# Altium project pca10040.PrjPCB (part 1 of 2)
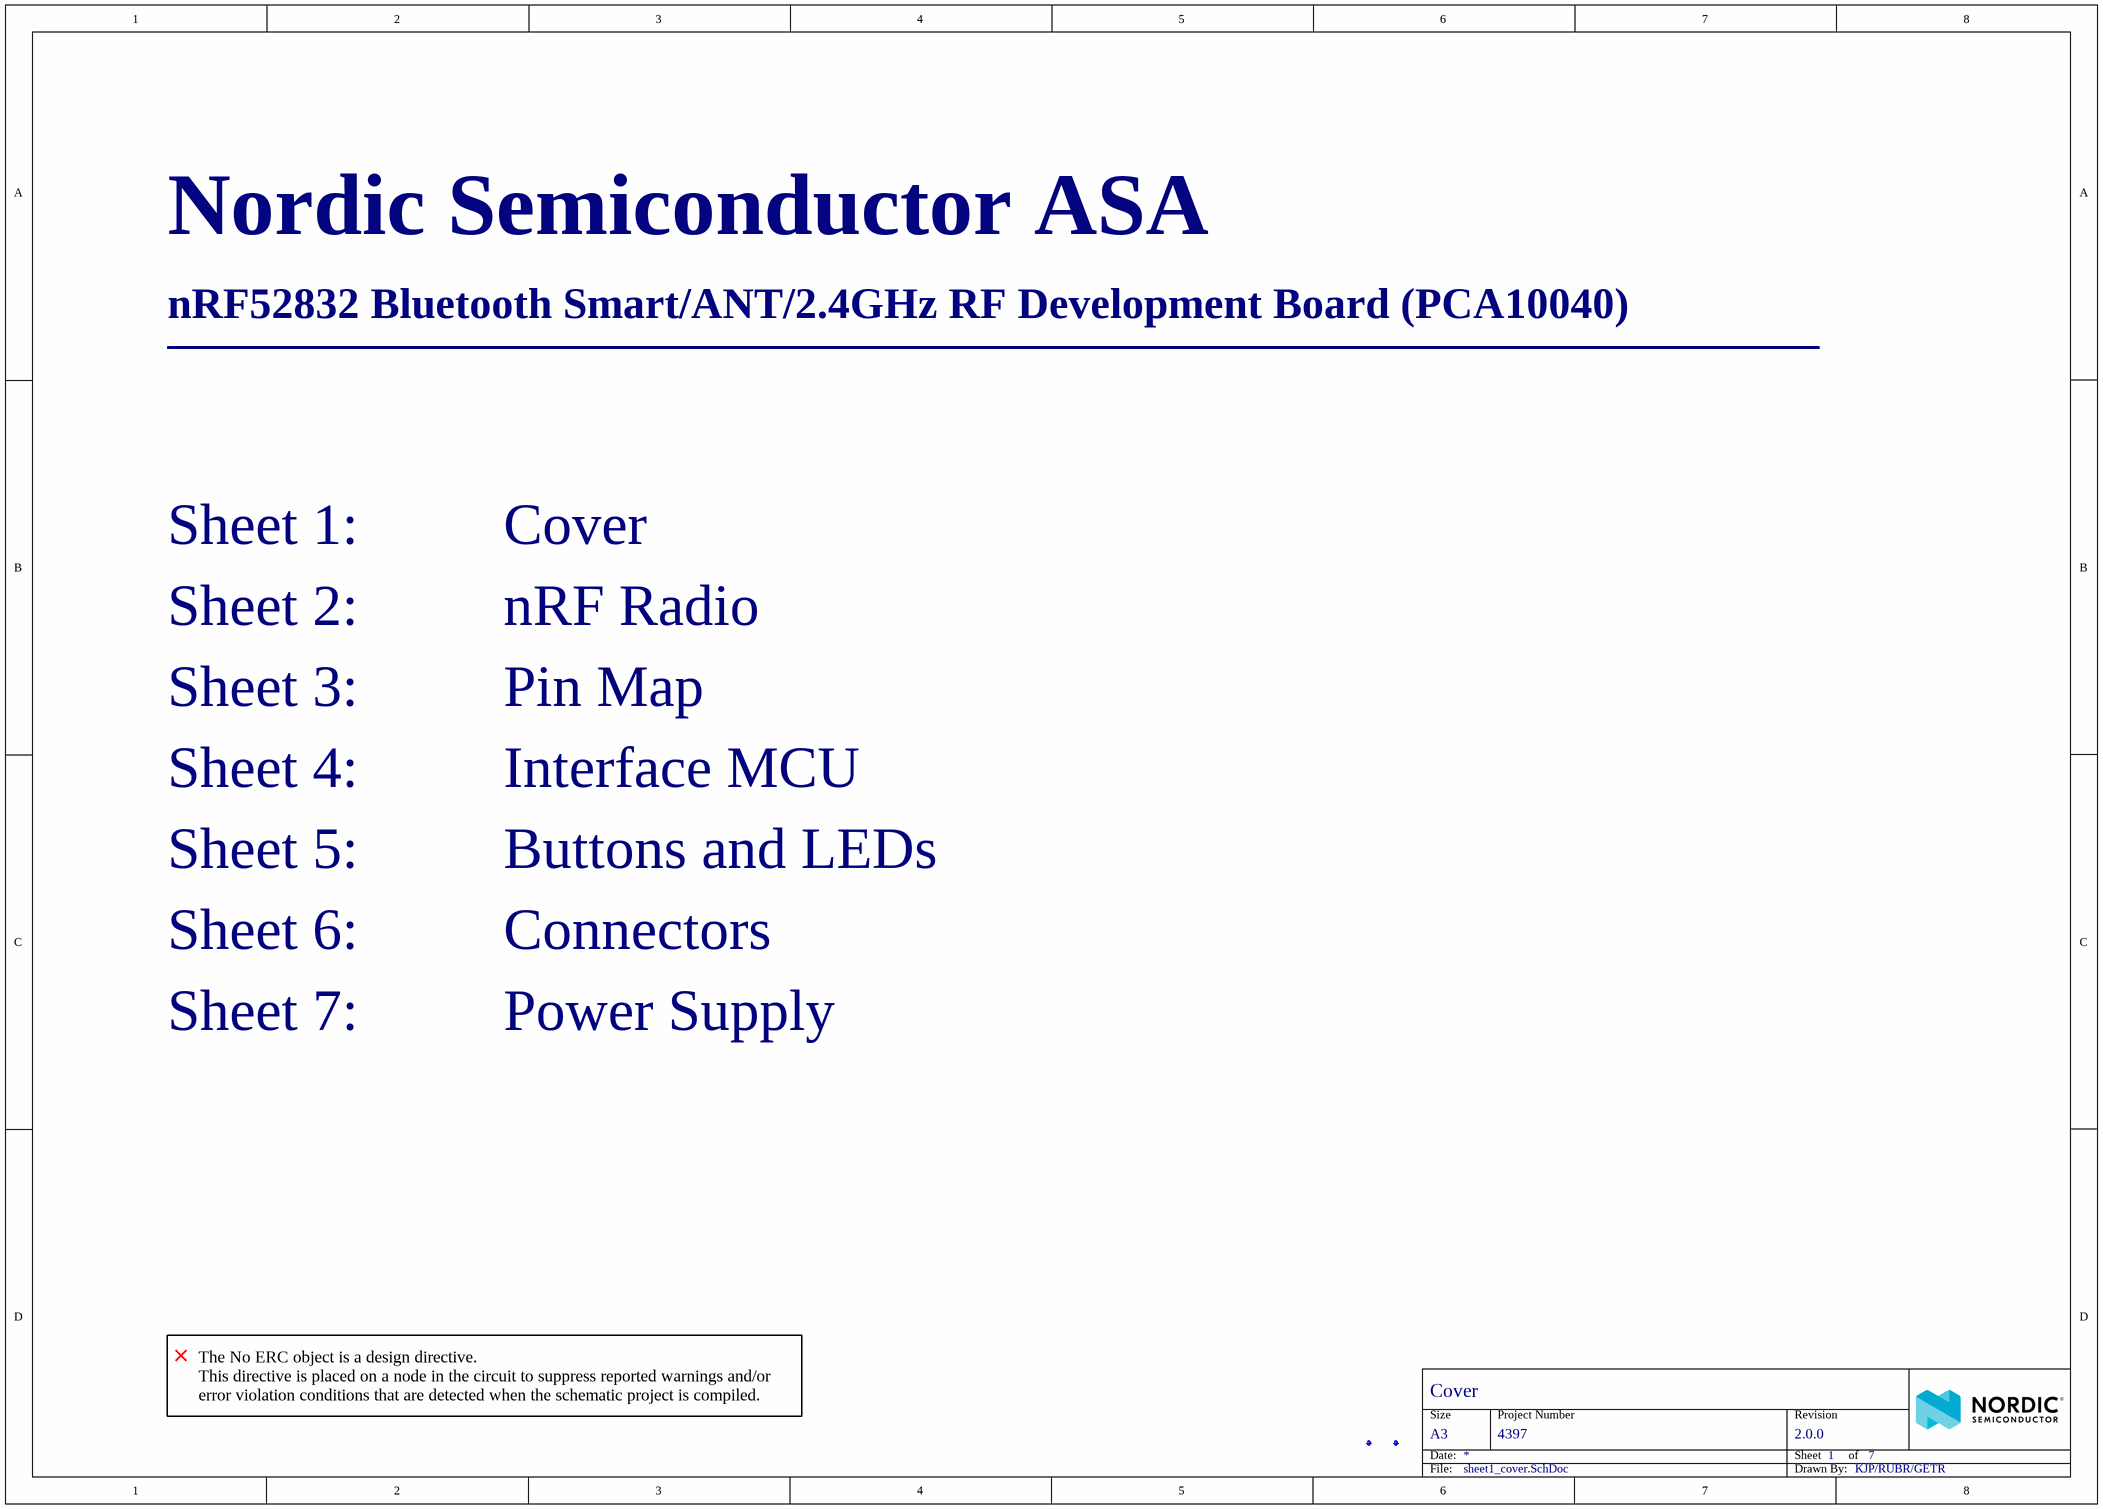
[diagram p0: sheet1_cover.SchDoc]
7 sheets, 248 parts. Net scope: global (net labels, ports and power ports of the same name join across sheets).
Board file: 400150.PcbDoc
Sheets:
  sheet1_cover.SchDoc
  sheet2_radio.SchDoc
  sheet3_pin_map.SchDoc
  sheet4_interface_mcu.SchDoc
  sheet5_buttons_and_leds.SchDoc
  sheet6_connectors.SchDoc
  sheet7_power_supply.SchDoc

## Sheet sheet1_cover.SchDoc: Cover
size A3; Organization: Nordic Semiconductor; DocumentNumber: 1; Revision: 2.0.0; SheetNumber: 1; SheetTotal: 7; CompanyName: Nordic Semiconductor; DrawnBy: KJP/RUBR/GETR; ProjectNumber: 4397; DocumentSize: A3; PCBRevision: 0111GETR; PCAName: PCA10040; PCBNumber: 400150

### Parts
Fid1  Fiducial mark  [Fiducial]  (value not drawn)
Fid2  Fiducial mark  [Fiducial]  (value not drawn)

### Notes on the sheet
- Nordic Semiconductor ASA
- nRF52832 Bluetooth Smart/ANT/2.4GHz RF Development Board (PCA10040)
- ________________________________________________________
- Sheet 1:          Cover
- Sheet 2:          nRF Radio
- Sheet 3:          Pin Map
- Sheet 4:          Interface MCU
- Sheet 5:          Buttons and LEDs
- Sheet 6:          Connectors
- Sheet 7:          Power Supply
- The No ERC object is a design directive.
  This directive is placed on a node in the circuit to suppress reported warnings and/or error violation conditions that are detected when the schematic project is compiled.

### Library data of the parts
Fid1 Fid2 = Fid-Mark: Artikkelnr Noca: N.A.

## Sheet sheet2_radio.SchDoc: nRF Radio
size A4; Organization: Nordic Semiconductor; DocumentNumber: 2; Revision: 2.0.0; SheetNumber: 2; SheetTotal: 7; CompanyName: Nordic Semiconductor; DrawnBy: KJP/RUBR/GETR; ProjectNumber: 4397; PCBRevision: 0111GETR; DocumentSize: A4; PCAName: PCA10040; PCBNumber: 400150
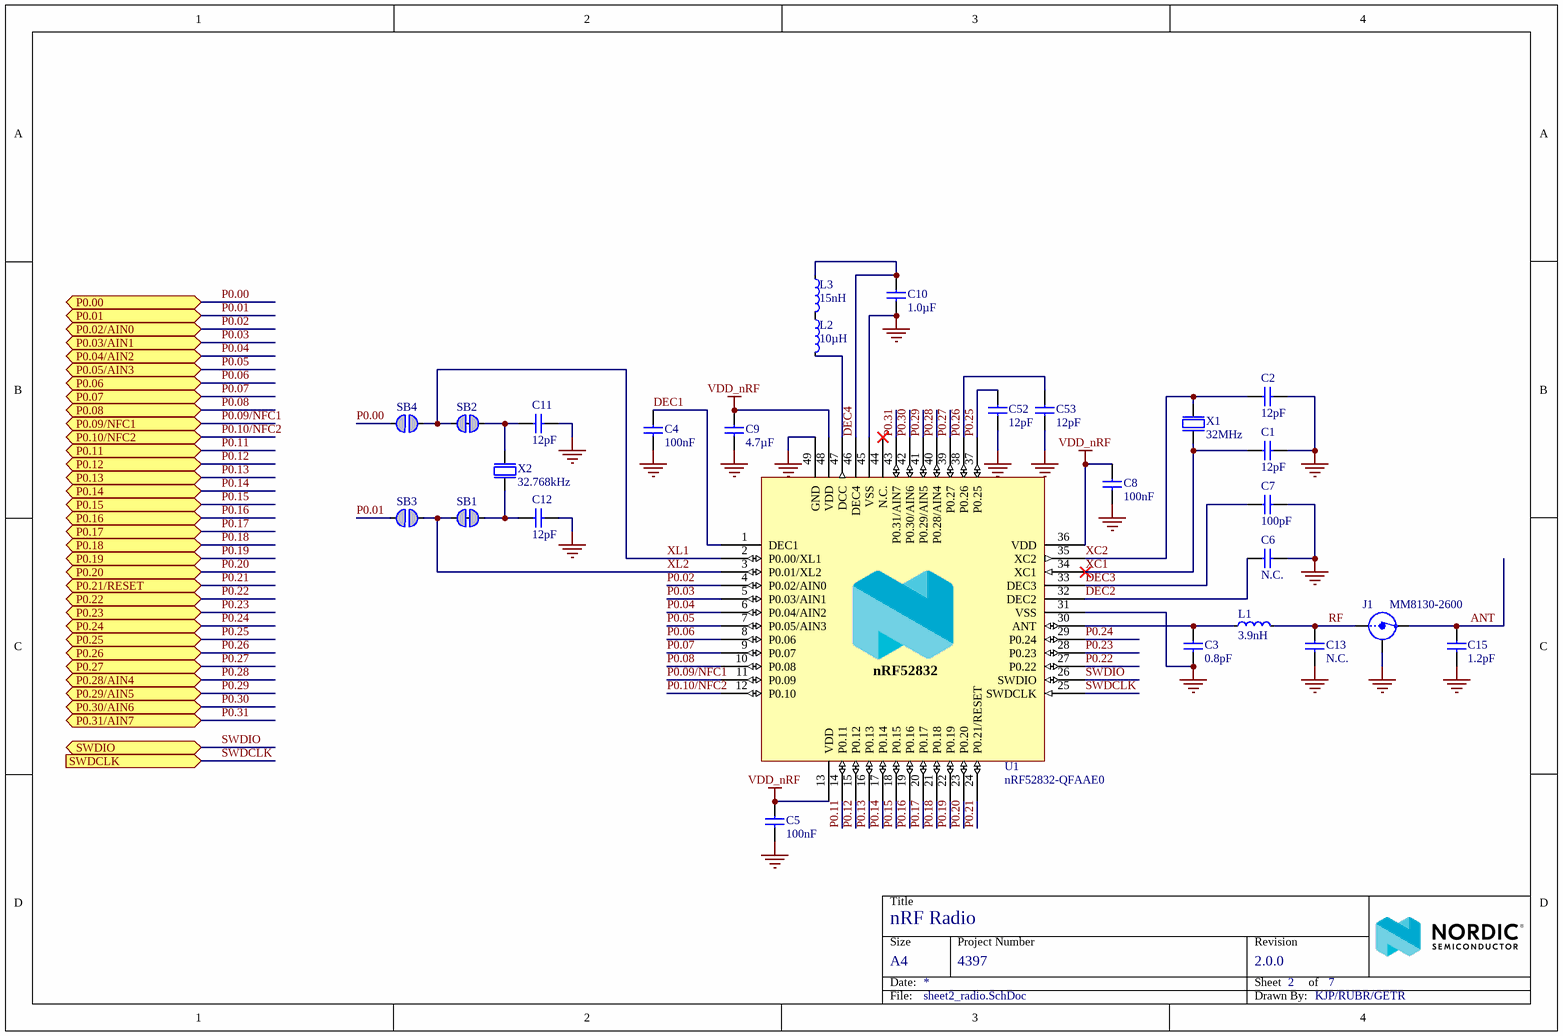
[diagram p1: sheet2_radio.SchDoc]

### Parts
C1  12pF  [CAPC1005X04L]
C2  12pF  [CAPC1005X04L]
C3  0.8pF  [CAPC1005X04L]
C4  100nF  [CAPC1005X04L]
C5  100nF  [CAPC1005X04L]
C6  N.C.  [CAPC1005X04L]
C7  100pF  [CAPC1005X04L]
C8  100nF  [CAPC1005X04L]
C9  4.7µF  [CAPC1608X06L]
C10  1.0µF  [CAPC1608X06L]
C11  12pF  [CAPC1005X04L]
C12  12pF  [CAPC1005X04L]
C13  N.C.  [CAPC1005X04L]
C15  1.2pF  [CAPC1005X04L]
C52  12pF  [CAPC1005X04L]
C53  12pF  [CAPC1005X04L]
J1  MM8130-2600  [COAXIAL-SWF]
L1  3.9nH  [INDC1005X04L]
L2  10µH  [INDC1608X06L]
L3  15nH  [INDC1005X04L]
SB1  Solderbridge  [Solderbridge_Shorted]  (value not drawn)  (net tie, no BOM)
SB2  Solderbridge  [Solderbridge_Shorted]  (value not drawn)  (net tie, no BOM)
SB3  Solderbridge  [Solderbridge]  (value not drawn)  (no BOM)
SB4  Solderbridge  [Solderbridge]  (value not drawn)  (no BOM)
U1  nRF52832-QFAAE0  [QFN40P600X600X90-48N]
X1  32MHz  [BT-XTAL_2016]
X2  32.768kHz  [XTAL_3215]

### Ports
P0.00 (bidir), P0.01 (bidir), P0.02/AIN0 (bidir), P0.03/AIN1 (bidir), P0.04/AIN2 (bidir), P0.05/AIN3 (bidir), P0.06 (bidir), P0.07 (bidir), P0.08 (bidir), P0.09/NFC1 (bidir), P0.10/NFC2 (bidir), P0.11 (bidir), P0.12 (bidir), P0.13 (bidir), P0.14 (bidir), P0.15 (bidir), P0.16 (bidir), P0.17 (bidir), P0.18 (bidir), P0.19 (bidir), P0.20 (bidir), P0.21/RESET (bidir), P0.22 (bidir), P0.23 (bidir), P0.24 (bidir), P0.25 (bidir), P0.26 (bidir), P0.27 (bidir), P0.28/AIN4 (bidir), P0.29/AIN5 (bidir), P0.30/AIN6 (bidir), P0.31/AIN7 (bidir), SWDCLK (in), SWDIO (bidir)

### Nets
GND: C1.2 C2.2 C3.1 C4.2 C5.2 C6.2 C7.2 C8.2 C9.2 C10.1 C11.1 C12.1 C13.2 C15.2 C52.2 C53.2 J1.2(Shield) U1.31(VSS) U1.45(VSS) U1.49(GND) X1.2(GND) X1.4(GND)
VDD_nRF: C5.1 C8.1 C9.1 U1.13(VDD) U1.36(VDD) U1.48(VDD)
ANT: C15.1 J1.3(OUT)
DEC1: C4.1 U1.1(DEC1)
DEC2: C6.1 U1.32(DEC2)
DEC3: C7.1 U1.33(DEC3)
DEC4: C10.2 L3.1 U1.46(DEC4)
P0.00: SB4.2 ; port P0.00
P0.01: SB3.2 ; port P0.01
P0.02: U1.4(P0.02/AIN0) ; port P0.02/AIN0
P0.03: U1.5(P0.03/AIN1) ; port P0.03/AIN1
P0.04: U1.6(P0.04/AIN2) ; port P0.04/AIN2
P0.05: U1.7(P0.05/AIN3) ; port P0.05/AIN3
P0.06: U1.8(P0.06) ; port P0.06
P0.07: U1.9(P0.07) ; port P0.07
P0.08: U1.10(P0.08) ; port P0.08
P0.09/NFC1: U1.11(P0.09) ; port P0.09/NFC1
P0.10/NFC2: U1.12(P0.10) ; port P0.10/NFC2
P0.11: U1.14(P0.11) ; port P0.11
P0.12: U1.15(P0.12) ; port P0.12
P0.13: U1.16(P0.13) ; port P0.13
P0.14: U1.17(P0.14) ; port P0.14
P0.15: U1.18(P0.15) ; port P0.15
P0.16: U1.19(P0.16) ; port P0.16
P0.17: U1.20(P0.17) ; port P0.17
P0.18: U1.21(P0.18) ; port P0.18
P0.19: U1.22(P0.19) ; port P0.19
P0.20: U1.23(P0.20) ; port P0.20
P0.21: U1.24(P0.21/RESET) ; port P0.21/RESET
P0.22: U1.27(P0.22) ; port P0.22
P0.23: U1.28(P0.23) ; port P0.23
P0.24: U1.29(P0.24) ; port P0.24
P0.25: C52.1 U1.37(P0.25) ; port P0.25
P0.26: C53.1 U1.38(P0.26) ; port P0.26
P0.27: U1.39(P0.27) ; port P0.27
P0.28: U1.40(P0.28/AIN4) ; port P0.28/AIN4
P0.29: U1.41(P0.29/AIN5) ; port P0.29/AIN5
P0.30: U1.42(P0.30/AIN6) ; port P0.30/AIN6
P0.31: U1.43(P0.31/AIN7) ; port P0.31/AIN7
RF: C13.1 J1.1(IN) L1.2
SWDCLK: U1.25(SWDCLK) ; port SWDCLK
SWDIO: U1.26(SWDIO) ; port SWDIO
XC1: C1.1 U1.34(XC1) X1.1(inp)
XC2: C2.1 U1.35(XC2) X1.3(out)
XL1: SB2.2 SB4.1 U1.2(P0.00/XL1)
XL2: SB1.2 SB3.1 U1.3(P0.01/XL2)
NetC3_2: C3.2 L1.1 U1.30(ANT)
NetC11_2: C11.2 SB2.1 X2.1(inp)
NetC12_2: C12.2 SB1.1 X2.2(out)
NetL2_1: L2.1 L3.2
NetL2_2: L2.2 U1.47(DCC)

Not connected (* = marked no-connect by the designer): U1 44(N.C.)*

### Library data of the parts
C1 C2 C11 C12 C52 C53 = C0402-12p: Capacitor, NP0, ±2%; Part number IPS: 00000002398; Note: 50V; Artikkelnr Noca: 20029159; Artikkelnr Simpro: N.A.
C3 = C0402-0.8p: Capacitor, NP0, ±5%; Part number IPS: 00000007782; Note: 50V; Artikkelnr Noca: 20029147; Artikkelnr Simpro: N.A.
C4 C5 C8 = C0402-100n: Capacitor, X7R, ±10%; Part number IPS: 00000005296; Note: 16V; Artikkelnr Noca: 20039200; Artikkelnr Simpro: N.A.
C6 C13 = C0402-N.C.: Not mounted; Note: Chip Cap; Artikkelnr Noca: N.A.; Assembly: Not mounted
C7 = C0402-100p: Capacitor, NP0, ±5%; Part number IPS: 00000002361; Note: 50V; Artikkelnr Noca: 20029135; Artikkelnr Simpro: N.A.
C9 = C0603-4µ7: Capacitor, X5R, ±10%; Part number IPS: 00000007783; Note: 6.3V; Artikkelnr Noca: 20069060; Artikkelnr Simpro: N.A.
C10 = C0603-1µ0: Capacitor, X7R, ±10%; Part number IPS: 00000000616; Note: 16V; Artikkelnr Noca: 20039335; Artikkelnr Simpro: N.A.
C15 = C0402-1.2p: Capacitor, NP0, ±0.1pF; Part number IPS: 00000005410; Note: 50V; Artikkelnr Noca: 20029157; Artikkelnr Simpro: N.A.
J1 = MM8130-2600: Coaxial Connector with Switch; Manufacturer: Murata; 2nd source part number: 81-MM8130-2600RA2; Artikkelnr Noca: 55029011; Artikkelnr Simpro: N.A.
L1 = L0402-3n9: Inductor, 170mA, ±0.1nH; Manufacturer: Murata; Manufacturer Part Number: LQP15MN3N9B02D; Part number IPS: 00000007793; Note: High frequency chip inductor ±5%; Artikkelnr Noca: 33029151; Artikkelnr Simpro: N.A.
L2 = L0603-10µ: Inductor, 80mA, ±10%; Manufacturer: Taiyo Yuden; Manufacturer Part Number: LBMF1608T100K; 2nd source part number: 178-6105; Part number IPS: 00000007794; Note: LBMF1608T100K 10µH 80mA 0603; Artikkelnr Noca: 33029314; Artikkelnr Simpro: N.A.
L3 = L0402-15n: Inductor, 320mA, ±5%; Manufacturer: Taiyo Yuden; Manufacturer Part Number: HK100515NJ-T; 2nd source part number: 658-1328; Part number IPS: 00000003215; Note: High frequency chip inductor ±10%; Artikkelnr Noca: 33029323; Artikkelnr Simpro: N.A.
SB1 SB2 = Solderbridge Shorted: Shorted Solderbridge; Artikkelnr Noca: N.A.
SB3 SB4 = Solderbridge: Artikkelnr Noca: N.A.
U1 = nRF52832-QFAAE0: Multi-protocol Bluetooth Low Energy, ANT and 2.4GHz proprietary system-on-chip; Manufacturer: Nordic Semiconductor; Artikkelnr Noca: N.A.
X1 = XTAL_SMD2016_32MHz_8pF_Epson: XTAL SMD 2016, 32MHz, Cl=8pF, Tol: ±10ppm, Stab: ±10ppm; Manufacturer: Epson Toyocom; Manufacturer Part Number: Q22FA12800025; Note: XTAL SMD 32.000MHz; Artikkelnr Noca: 22019238; Artikkelnr Simpro: N.A.
X2 = XTAL_FC-135 32.768k: XTAL SMD 3215, 32.768kHz, 9pF, ±20ppm; Manufacturer: Epson Toyocom; Manufacturer Part Number: FC-135 32.768KHZ ±20PPM,9.0PF; 2nd source part number: 127-8037; Note: XTAL SMD 32.768kHz, 3215; Artikkelnr Noca: 22019091; Artikkelnr Simpro: N.A.

## Sheet sheet3_pin_map.SchDoc: Pin Map
size A4; Organization: Nordic Semiconductor; DocumentNumber: 3; Revision: 2.0.0; SheetNumber: 3; SheetTotal: 7; CompanyName: Nordic Semiconductor; DrawnBy: RUBR/GETR; ProjectNumber: 4397; PCBRevision: 0111GETR; DocumentSize: A4; PCAName: PCA10040; PCBNumber: 400150
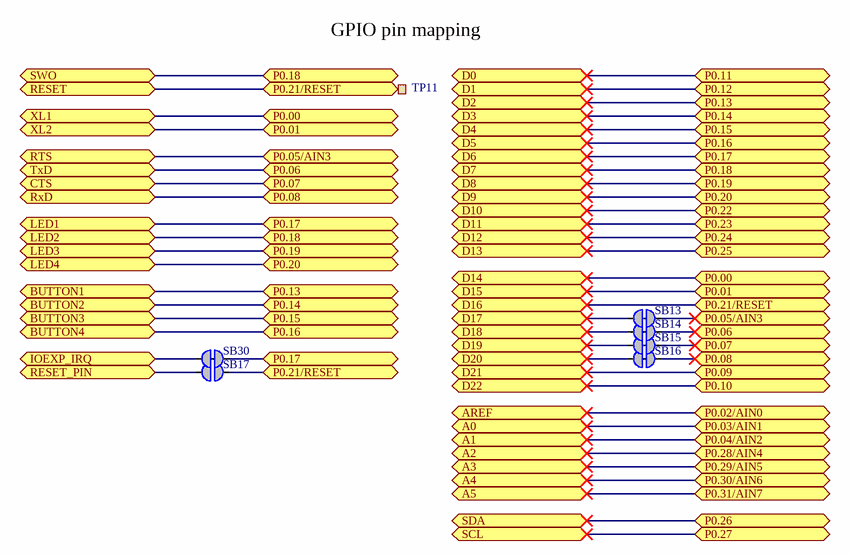
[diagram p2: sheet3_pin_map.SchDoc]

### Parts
SB13  Solderbridge  [Solderbridge_Shorted]  (value not drawn)  (net tie, no BOM)
SB14  Solderbridge  [Solderbridge_Shorted]  (value not drawn)  (net tie, no BOM)
SB15  Solderbridge  [Solderbridge_Shorted]  (value not drawn)  (net tie, no BOM)
SB16  Solderbridge  [Solderbridge_Shorted]  (value not drawn)  (net tie, no BOM)
SB17  Solderbridge  [Solderbridge]  (value not drawn)  (no BOM)
SB30  Solderbridge  [Solderbridge_Shorted]  (value not drawn)  (net tie, no BOM)
TP11  Ø1.0mm,SMD  [TP_SMD_Ø1.0mm]  (value not drawn)  (no BOM)

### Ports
A0 (bidir), A1 (bidir), A2 (bidir), A3 (bidir), A4 (bidir), A5 (bidir), AREF (bidir), BUTTON1 (bidir), BUTTON2 (bidir), BUTTON3 (bidir), BUTTON4 (bidir), CTS (bidir), D0 (bidir), D1 (bidir), D2 (bidir), D3 (bidir), D4 (bidir), D5 (bidir), D6 (bidir), D7 (bidir), D8 (bidir), D9 (bidir), D10 (bidir), D11 (bidir), D12 (bidir), D13 (bidir), D14 (bidir), D15 (bidir), D16 (bidir), D17 (bidir), D18 (bidir), D19 (bidir), D20 (bidir), D21 (bidir), D22 (bidir), IOEXP_IRQ (bidir), LED1 (bidir), LED2 (bidir), LED3 (bidir), LED4 (bidir), P0.00 (bidir), P0.01 (bidir), P0.02/AIN0 (bidir), P0.03/AIN1 (bidir), P0.04/AIN2 (bidir), P0.05/AIN3 (bidir), P0.06 (bidir), P0.07 (bidir), P0.08 (bidir), P0.09 (bidir), P0.10 (bidir), P0.11 (bidir), P0.12 (bidir), P0.13 (bidir), P0.14 (bidir), P0.15 (bidir), P0.16 (bidir), P0.17 (bidir), P0.18 (bidir), P0.19 (bidir), P0.20 (bidir), P0.21/RESET (bidir), P0.22 (bidir), P0.23 (bidir), P0.24 (bidir), P0.25 (bidir), P0.26 (bidir), P0.27 (bidir), P0.28/AIN4 (bidir), P0.29/AIN5 (bidir), P0.30/AIN6 (bidir), P0.31/AIN7 (bidir), RESET (bidir), RESET_PIN (bidir), RTS (bidir), RxD (bidir), SCL (bidir), SDA (bidir), SWO (bidir), TxD (bidir), XL1 (bidir), XL2 (bidir)

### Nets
D17: SB13.1 ; port D17
D18: SB14.1 ; port D18
D19: SB15.1 ; port D19
D20: SB16.1 ; port D20
D21: port D21, port P0.09
D22: port D22, port P0.10
IOEXP_IRQ: SB30.2 ; port IOEXP_IRQ
P0.00: port P0.00, port XL1, port D14
P0.01: port P0.01, port XL2, port D15
P0.02: port AREF, port P0.02/AIN0
P0.03: port A0, port P0.03/AIN1
P0.04: port A1, port P0.04/AIN2
P0.05: SB13.2 ; port P0.05/AIN3, port RTS
P0.06: SB14.2 ; port P0.06, port TxD
P0.07: SB15.2 ; port P0.07, port CTS
P0.08: SB16.2 ; port P0.08, port RxD
P0.11: port D0, port P0.11
P0.12: port D1, port P0.12
P0.13: port P0.13, port BUTTON1, port D2
P0.14: port P0.14, port BUTTON2, port D3
P0.15: port P0.15, port BUTTON3, port D4
P0.16: port P0.16, port BUTTON4, port D5
P0.17: SB30.1 ; port LED1, port D6, port P0.17
P0.18: port SWO, port P0.18, port LED2, port D7
P0.19: port LED3, port D8, port P0.19
P0.20: port LED4, port D9, port P0.20
P0.21: SB17.2 TP11.1 ; port RESET, port P0.21/RESET, port D16
P0.22: port D10, port P0.22
P0.23: port D11, port P0.23
P0.24: port D12, port P0.24
P0.25: port D13, port P0.25
P0.26: port P0.26, port SDA
P0.27: port P0.27, port SCL
P0.28: port A2, port P0.28/AIN4
P0.29: port A3, port P0.29/AIN5
P0.30: port A4, port P0.30/AIN6
P0.31: port A5, port P0.31/AIN7
RESET_PIN: SB17.1 ; port RESET_PIN

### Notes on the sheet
- (near TP11) GPIO pin mapping

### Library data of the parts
SB13-SB16 SB30 = Solderbridge Shorted: as SB1 on sheet sheet2_radio
SB17 = Solderbridge: Artikkelnr Noca: N.A.
TP11 = TP_SMD_Ø1.0MM: 1.0mm circular SMD testpad; Manufacturer: Nordic Semiconductor; Artikkelnr Noca: N.A.

## Sheet sheet4_interface_mcu.SchDoc: Interface MCU
size A3; Organization: Nordic Semiconductor; DocumentNumber: 4; Revision: 2.0.0; SheetNumber: 4; SheetTotal: 7; CompanyName: Nordic Semiconductor; DrawnBy: KJP/RUBR/GETR; ProjectNumber: 4397; PCAName: PCA10040; PCBRevision: 0111GETR; DocumentSize: A3; PCBNumber: 400150
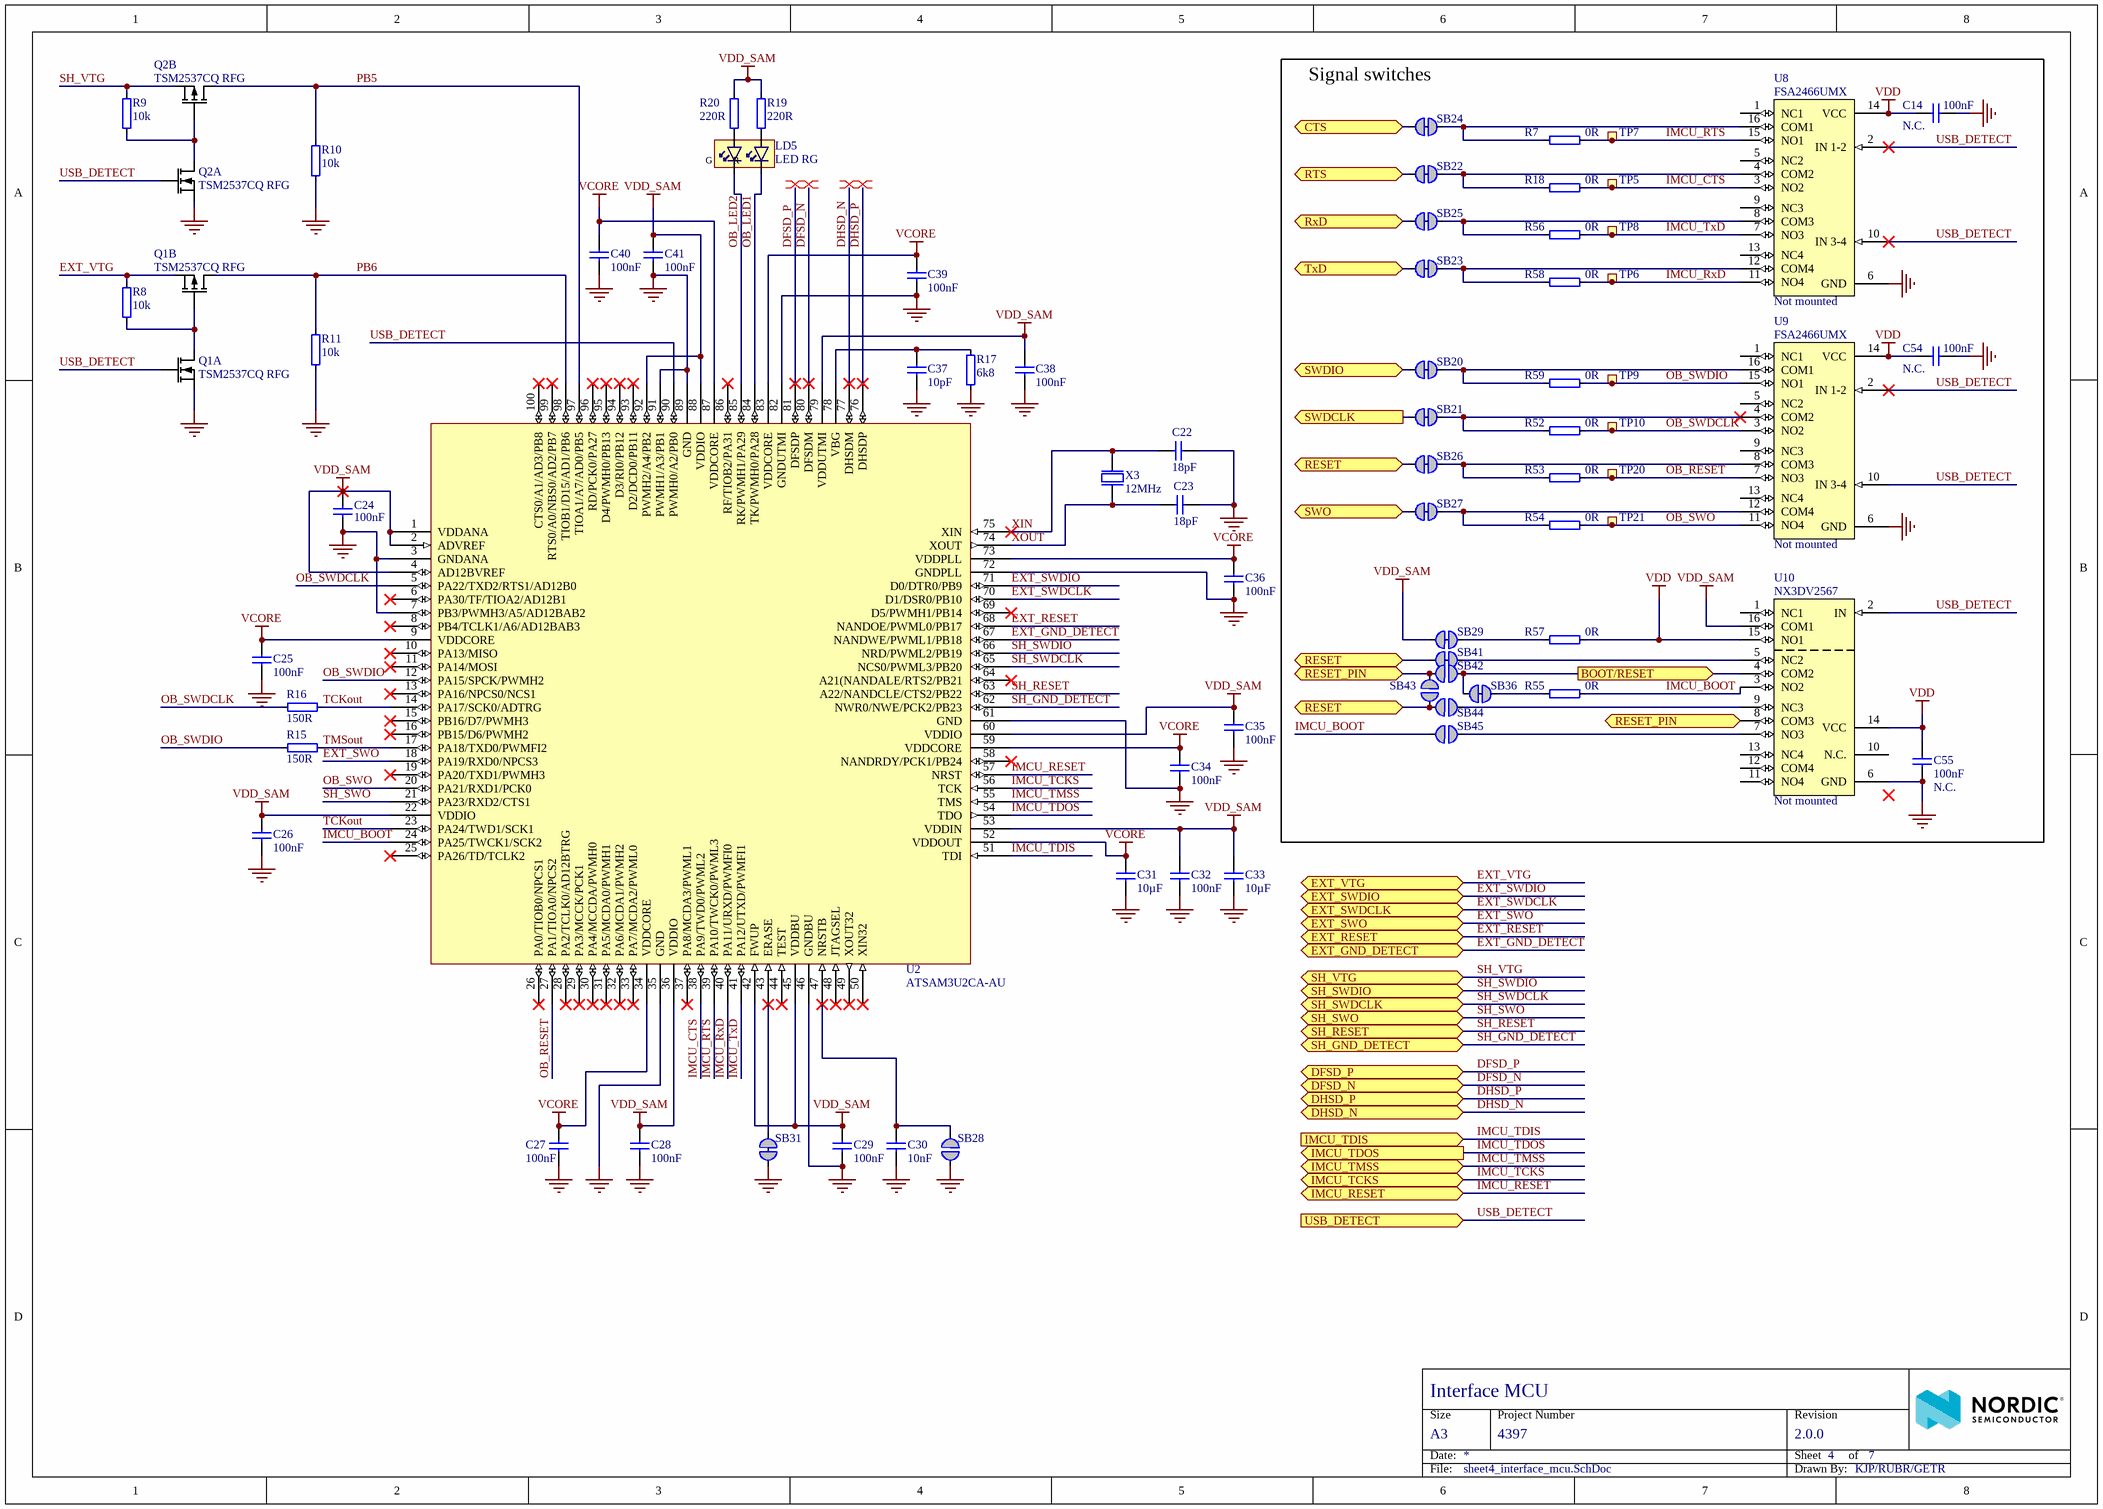
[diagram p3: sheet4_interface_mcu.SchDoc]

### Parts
C14  100nF  Assembly: N.C.  [CAPC1005X04L]
C22  18pF  [CAPC1005X04L]
C23  18pF  [CAPC1005X04L]
C24  100nF  [CAPC1005X04L]
C25  100nF  [CAPC1005X04L]
C26  100nF  [CAPC1005X04L]
C27  100nF  [CAPC1005X04L]
C28  100nF  [CAPC1005X04L]
C29  100nF  [CAPC1005X04L]
C30  10nF  [CAPC1005X04L]
C31  10µF  [CAPC1608X06L]
C32  100nF  [CAPC1005X04L]
C33  10µF  [CAPC1608X06L]
C34  100nF  [CAPC1005X04L]
C35  100nF  [CAPC1005X04L]
C36  100nF  [CAPC1005X04L]
C37  10pF  [CAPC1005X04L]
C38  100nF  [CAPC1005X04L]
C39  100nF  [CAPC1005X04L]
C40  100nF  [CAPC1005X04L]
C41  100nF  [CAPC1005X04L]
C54  100nF  Assembly: N.C.  [CAPC1005X04L]
C55  100nF  Assembly: N.C.  [CAPC1005X04L]
LD5  LED RG  [LED_DUAL_0606]
Q1  TSM2537CQ RFG  [DFN65P200X200X80_HS-6N]  (parts A,B of 2)
Q2  TSM2537CQ RFG  [DFN65P200X200X80_HS-6N]  (parts A,B of 2)
R7  0R  [RESC1005X04L]
R8  10k  [RESC1005X04L]
R9  10k  [RESC1005X04L]
R10  10k  [RESC1005X04L]
R11  10k  [RESC1005X04L]
R15  150R  [RESC1005X04L]
R16  150R  [RESC1005X04L]
R17  6k8  [RESC1005X04L]
R18  0R  [RESC1005X04L]
R19  220R  [RESC0603X03L_C]
R20  220R  [RESC0603X03L_C]
R52  0R  [RESC1005X04L]
R53  0R  [RESC1005X04L]
R54  0R  [RESC1005X04L]
R55  0R  [RESC1005X04L]
R56  0R  [RESC1005X04L]
R57  0R  [RESC1005X04L]
R58  0R  [RESC1005X04L]
R59  0R  [RESC1005X04L]
SB20  Solderbridge  [Solderbridge_Shorted]  (value not drawn)  (net tie, no BOM)
SB21  Solderbridge  [Solderbridge_Shorted]  (value not drawn)  (net tie, no BOM)
SB22  Solderbridge  [Solderbridge_Shorted]  (value not drawn)  (net tie, no BOM)
SB23  Solderbridge  [Solderbridge_Shorted]  (value not drawn)  (net tie, no BOM)
SB24  Solderbridge  [Solderbridge_Shorted]  (value not drawn)  (net tie, no BOM)
SB25  Solderbridge  [Solderbridge_Shorted]  (value not drawn)  (net tie, no BOM)
SB26  Solderbridge  [Solderbridge_Shorted]  (value not drawn)  (net tie, no BOM)
SB27  Solderbridge  [Solderbridge_Shorted]  (value not drawn)  (net tie, no BOM)
SB28  Solderbridge  [Solderbridge]  (value not drawn)  (no BOM)
SB29  Solderbridge  [Solderbridge_Shorted]  (value not drawn)  (net tie, no BOM)
SB31  Solderbridge  [Solderbridge_Shorted]  (value not drawn)  (net tie, no BOM)
SB36  Solderbridge  [Solderbridge_Shorted]  (value not drawn)  (net tie, no BOM)
SB41  Solderbridge  [Solderbridge_Shorted]  (value not drawn)  (net tie, no BOM)
SB42  Solderbridge  [Solderbridge]  (value not drawn)  (no BOM)
SB43  Solderbridge  [Solderbridge]  (value not drawn)  (no BOM)
SB44  Solderbridge  [Solderbridge]  (value not drawn)  (no BOM)
SB45  Solderbridge  [Solderbridge]  (value not drawn)  (no BOM)
TP5  Ø1.0mm,SMD  [TP_SMD_Ø1.0mm]  (value not drawn)  (no BOM)
TP6  Ø1.0mm,SMD  [TP_SMD_Ø1.0mm]  (value not drawn)  (no BOM)
TP7  Ø1.0mm,SMD  [TP_SMD_Ø1.0mm]  (value not drawn)  (no BOM)
TP8  Ø1.0mm,SMD  [TP_SMD_Ø1.0mm]  (value not drawn)  (no BOM)
TP9  Ø1.0mm,SMD  [TP_SMD_Ø1.0mm]  (value not drawn)  (no BOM)
TP10  Ø1.0mm,SMD  [TP_SMD_Ø1.0mm]  (value not drawn)  (no BOM)
TP20  Ø1.0mm,SMD  [TP_SMD_Ø1.0mm]  (value not drawn)  (no BOM)
TP21  Ø1.0mm,SMD  [TP_SMD_Ø1.0mm]  (value not drawn)  (no BOM)
U2  ATSAM3U2CA-AU  [TSQFP50P1600X1600X160-100N]
U8  FSA2466UMX  Assembly: Not mounted  [XQFN40P180X260X50-16N]
U9  FSA2466UMX  Assembly: Not mounted  [XQFN40P180X260X50-16N]
U10  NX3DV2567  Assembly: Not mounted  [XQFN40P180X260X50-16N]
X3  12MHz  [BT-XTAL_3225]

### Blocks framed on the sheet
Signal switches: C14 C54 C55 R7 R18 R52-R59 SB20-SB27 SB29 SB36 SB41-SB45 TP5-TP10 TP20 TP21 U8-U10

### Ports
BOOT/RESET (out), CTS (bidir), DFSD_N (bidir), DFSD_P (bidir), DHSD_N (bidir), DHSD_P (bidir), EXT_GND_DETECT (bidir), EXT_RESET (bidir), EXT_SWDCLK (bidir), EXT_SWDIO (bidir), EXT_SWO (bidir), EXT_VTG (bidir), IMCU_RESET (bidir), IMCU_TCKS (bidir), IMCU_TDIS (in), IMCU_TDOS (out), IMCU_TMSS (bidir), RESET (bidir), RESET_PIN (bidir), RTS (bidir), RxD (bidir), SH_GND_DETECT (bidir), SH_RESET (bidir), SH_SWDCLK (bidir), SH_SWDIO (bidir), SH_SWO (bidir), SH_VTG (bidir), SWDCLK (out), SWDIO (bidir), SWO (bidir), TxD (bidir), USB_DETECT (in)

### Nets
GND: C14.1 C22.2 C23.2 C24.1 C25.1 C26.1 C27.1 C28.1 C29.1 C30.1 C31.1 C32.1 C33.1 C34.1 C35.1 C36.2 C37.1 C38.1 C39.1 C40.1 C41.1 C54.1 C55.1 Q1.1(S1) Q2.1(S1) R10.1 R11.1 R17.1 SB28.2 SB31.2 U2.3(GNDANA) U2.7(PB3/PWMH3/A5/AD12BAB2) U2.35(GND) U2.46(GNDBU) U2.61(GND) U2.72(GNDPLL) U2.82(GNDUTMI) U2.89(GND) U2.91(PWMH1/A3/PB1) U8.6(GND) U9.6(GND) U10.6(GND) X3.2(GND) X3.4(GND)
VCORE: C25.2 C27.2 C31.2 C34.2 C36.1 C39.2 C40.2 U2.9(VDDCORE) U2.34(VDDCORE) U2.52(VDDOUT) U2.59(VDDCORE) U2.73(VDDPLL) U2.83(VDDCORE) U2.87(VDDCORE)
VDD: C14.2 C54.2 C55.2 R57.2 U8.14(VCC) U9.14(VCC) U10.14(VCC) U10.15(NO1)
VDD_SAM: C24.2 C26.2 C28.2 C29.2 C32.2 C33.2 C35.2 C38.2 C41.2 R19.2 R20.2 SB29.2 U2.1(VDDANA) U2.2(ADVREF) U2.4(AD12BVREF) U2.22(VDDIO) U2.36(VDDIO) U2.42(FWUP) U2.45(VDDBU) U2.53(VDDIN) U2.60(VDDIO) U2.79(VDDUTMI) U2.88(VDDIO) U2.92(PWMH2/A4/PB2) U10.16(COM1)
BOOT/RESET: SB36.2 SB42.1 U10.4(COM2) ; port BOOT/RESET
DFSD_N: U2.80(DFSDM) ; port DFSD_N
DFSD_P: U2.81(DFSDP) ; port DFSD_P
DHSD_N: U2.77(DHSDM) ; port DHSD_N
DHSD_P: U2.76(DHSDP) ; port DHSD_P
EXT_GND_DETECT: U2.67(NANDWE/PWML1/PB18) ; port EXT_GND_DETECT
EXT_RESET: U2.68(NANDOE/PWML0/PB17) ; port EXT_RESET
EXT_SWDCLK: U2.70(D1/DSR0/PB10) ; port EXT_SWDCLK
EXT_SWDIO: U2.71(D0/DTR0/PB9) ; port EXT_SWDIO
EXT_SWO: U2.18(PA19/RXD0/NPCS3) ; port EXT_SWO
EXT_VTG: Q1.4(S2) R8.1 ; port EXT_VTG
IMCU_BOOT: R55.2 SB45.2 U2.24(PA25/TWCK1/SCK2) U10.3(NO2)
IMCU_CTS: R18.2 TP5.1 U2.38(PA9/TWD0/PWML2) U8.3(NO2)
IMCU_RESET: U2.57(NRST) ; port IMCU_RESET
IMCU_RTS: R7.2 TP7.1 U2.39(PA10/TWCK0/PWML3) U8.15(NO1)
IMCU_RxD: R58.2 TP6.1 U2.40(PA11/URXD/PWMFI0) U8.11(NO4)
IMCU_TCKS: U2.56(TCK) ; port IMCU_TCKS
IMCU_TDIS: U2.51(TDI) ; port IMCU_TDIS
IMCU_TDOS: U2.54(TDO) ; port IMCU_TDOS
IMCU_TMSS: U2.55(TMS) ; port IMCU_TMSS
IMCU_TxD: R56.2 TP8.1 U2.41(PA12/UTXD/PWMFI1) U8.7(NO3)
OB_LED1: LD5.4(C1) U2.84(TK/PWMH0/PA28)
OB_LED2: LD5.3(C2) U2.85(RK/PWMH1/PA29)
OB_RESET: R53.2 TP20.1 U2.27(PA1/TIOA0/NPCS2) U9.7(NO3)
OB_SWDCLK: R16.2 R52.2 TP10.1 U2.5(PA22/TXD2/RTS1/AD12B0) U9.3(NO2)
OB_SWDIO: R15.2 R59.2 TP9.1 U2.12(PA15/SPCK/PWMH2) U9.15(NO1)
OB_SWO: R54.2 TP21.1 U2.20(PA21/RXD1/PCK0) U9.11(NO4)
P0.05: SB22.2 ; port RTS
P0.06: SB23.2 ; port TxD
P0.07: SB24.2 ; port CTS
P0.08: SB25.2 ; port RxD
P0.18: SB27.2 ; port SWO
P0.21: SB26.2 SB41.2 SB43.2 SB44.2 ; port RESET
PB5: Q2.3(D2) R10.2 U2.97(TIOA1/A7/AD0/PB5)
PB6: Q1.3(D2) R11.2 U2.98(TIOB1/D15/AD1/PB6)
RESET_PIN: SB42.2 SB43.1 U10.8(COM3) ; port RESET_PIN
SH_GND_DETECT: U2.62(NWR0/NWE/PCK2/PB23) ; port SH_GND_DETECT
SH_RESET: U2.63(A22/NANDCLE/CTS2/PB22) ; port SH_RESET
SH_SWDCLK: U2.65(NCS0/PWML3/PB20) ; port SH_SWDCLK
SH_SWDIO: U2.66(NRD/PWML2/PB19) ; port SH_SWDIO
SH_SWO: U2.21(PA23/RXD2/CTS1) ; port SH_SWO
SH_VTG: Q2.4(S2) R9.1 ; port SH_VTG
SWDCLK: SB21.2 ; port SWDCLK
SWDIO: SB20.2 ; port SWDIO
TCKout: R16.1 U2.14(PA17/SCK0/ADTRG) U2.23(PA24/TWD1/SCK1)
TMSout: R15.1 U2.17(PA18/TXD0/PWMFI2)
USB_DETECT: Q1.2(G1) Q2.2(G1) U2.90(PWMH0/A2/PB0) U8.2(IN_1-2) U8.10(IN_3-4) U9.2(IN_1-2) U9.10(IN_3-4) U10.2(IN) ; port USB_DETECT
XIN: C22.1 U2.75(XIN) X3.3(out)
XOUT: C23.1 U2.74(XOUT) X3.1(inp)
NetC30_2: C30.2 SB28.1 U2.47(NRSTB)
NetC37_2: C37.2 R17.2 U2.78(VBG)
NetLD5_1: LD5.1(A2) R20.1
NetLD5_2: LD5.2(A1) R19.1
NetQ1_5: Q1.5(G2) Q1.6(D1) R8.2
NetQ2_5: Q2.5(G2) Q2.6(D1) R9.2
NetR7_1: R7.1 SB24.1 U8.16(COM1)
NetR18_1: R18.1 SB22.1 U8.4(COM2)
NetR52_1: R52.1 SB21.1 U9.4(COM2)
NetR53_1: R53.1 SB26.1 U9.8(COM3)
NetR54_1: R54.1 SB27.1 U9.12(COM4)
NetR55_1: R55.1 SB36.1
NetR56_1: R56.1 SB25.1 U8.8(COM3)
NetR57_1: R57.1 SB29.1
NetR58_1: R58.1 SB23.1 U8.12(COM4)
NetR59_1: R59.1 SB20.1 U9.16(COM1)
NetSB31_1: SB31.1 U2.43(ERASE)
NetSB41_1: SB41.1 U10.5(NC2)
NetSB44_1: SB44.1 U10.9(NC3)
NetSB45_1: SB45.1 U10.7(NO3)

Not connected (* = marked no-connect by the designer): U2 6(PA30/TF/TIOA2/AD12B1)* 8(PB4/TCLK1/A6/AD12BAB3)* 10(PA13/MISO)* 11(PA14/MOSI)* 13(PA16/NPCS0/NCS1)* 15(PB16/D7/PWMH3)* 16(PB15/D6/PWMH2)* 19(PA20/TXD1/PWMH3)* 25(PA26/TD/TCLK2)* 26(PA0/TIOB0/NPCS1)* 28(PA2/TCLK0/AD12BTRG)* 29(PA3/MCCK/PCK1)* 30(PA4/MCCDA/PWMH0)* 31(PA5/MCDA0/PWMH1)* 32(PA6/MCDA1/PWMH2)* 33(PA7/MCDA2/PWML0)* 37(PA8/MCDA3/PWML1)* 44(TEST)* 48(JTAGSEL)* 49(XOUT32)* 50(XIN32)* 58(NANDRDY/PCK1/PB24)* 64(A21(NANDALE/RTS2/PB21)* 69(D5/PWMH1/PB14)* 86(RF/TIOB2/PA31)* 93(D2/DCD0/PB11)* 94(D3/RI0/PB12)* 95(D4/PWMH0/PB13)* 96(RD/PCK0/PA27)* 99(RTS0/A0/NBS0/AD2/PB7)* 100(CTS0/A1/AD3/PB8)*; U8 1(NC1) 5(NC2) 9(NC3) 13(NC4); U9 1(NC1) 5(NC2) 9(NC3) 13(NC4); U10 1(NC1) 10(N.C.) 11(NO4) 12(COM4) 13(NC4)

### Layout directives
differential pair: DFSD_N, DFSD_P, DHSD_N, DHSD_P

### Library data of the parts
C14 C24-C29 C32 C34-C36 C38-C41 C54 C55 = C0402-100n: as C4 on sheet sheet2_radio
C22 C23 = C0402-18p: Capacitor, NP0, ±5%; Note: 50V; Artikkelnr Noca: 20029209; Artikkelnr Simpro: N.A.
C30 = C0402-10n: Capacitor, X7R, ±10%; Part number IPS: 00000007784; Note: 16V; Artikkelnr Noca: 20039166; Artikkelnr Simpro: N.A.
C31 C33 = C0603-10µ: Capacitor, X5R, ±20%; Part number IPS: 00000007785; Note: 6.3V; Artikkelnr Noca: 20039234; Artikkelnr Simpro: N.A.
C37 = C0402-10p: Capacitor, NP0, ±2%; 2nd source part number: 185-6064; Note: 50V; Artikkelnr Noca: 20029260; Artikkelnr Simpro: N.A.
LD5 = LTST-C195KGJRKT: Ultra bright AlInGaP Bi-Color LED; Manufacturer: Lite-On Inc; 2nd source part number: 859-LTST-C195KGJRKT; Artikkelnr Noca: 13019145; Artikkelnr Simpro: N.A.
Q1 Q2 = TSM2537CQ RFG: Dual N & P Ch MOFET, 11.6A/9A, 90mOhm max, 6.25W; Manufacturer: Taiwan Semiconductor; Artikkelnr Noca: N.A.
R7 R18 R52-R59 = R0402-0R: Resistor, ±5%, 0.063W; Note: Chip Res 5%; Artikkelnr Noca: 27049000; Artikkelnr Simpro: N.A.; Value Ohm: 0
R8-R11 = R0402-10k: Resistor, ±1%, 0.063W; Part number IPS: 00000002093; Note: Chip Res 1%; Artikkelnr Noca: 27049097; Artikkelnr Simpro: N.A.; Value Ohm: 10000
R15 R16 = R0402-150: Resistor, ±1%, 0.063W; Note: Chip Res 1%; Artikkelnr Noca: 27049053; Artikkelnr Simpro: N.A.; Value Ohm: 150
R17 = R0402-6k8: Resistor, ±1%, 0.063W; Note: Chip Res 1%; Artikkelnr Noca: 27049093; Artikkelnr Simpro: N.A.; Value Ohm: 6800
R19 R20 = R0201-220: Resistor, ±1%, 0.05W; Part number IPS: 00000000863; Note: Chip Res 1%; Artikkelnr Noca: N.A.
SB20-SB27 SB29 SB31 SB36 SB41 = Solderbridge Shorted: as SB1 on sheet sheet2_radio
SB28 SB42-SB45 = Solderbridge: Artikkelnr Noca: N.A.
TP5-TP10 TP20 TP21 = TP_SMD_Ø1.0MM: as TP11 on sheet sheet3_pin_map
U2 = ATSAM3U2CA-AU: IC MCU 32bit 128kB flash 100LQFP; Manufacturer: Atmel; 2nd source part number: 184-1662; Artikkelnr Noca: 15019073; Artikkelnr Simpro: N.A.
U8 U9 = FSA2466UMX: Data / Audio Low-Voltage Dual DPDT Analog Switch; Manufacturer: Fairchild Semiconductor; 2nd source part number: 512-FSA2466UMX; Artikkelnr Noca: 15070069; Artikkelnr Simpro: N.A.
U10 = NX3DV2567GU: Low-ohmic four-pole double-throw analog switch; Manufacturer: NXP Semiconductors; 2nd source part number: 771-NX3DV2567GU115; Part number IPS: 00000007816; Artikkelnr Noca: 15079317; Artikkelnr Simpro: N.A.
X3 = XTAL_SMD3225_12MHz_18pF_TXC: XTAL SMD 3225, 12MHz, Cl=18pF, Tol: ±30ppm, Stab: ±30ppm; Manufacturer: TXC Corporation; Manufacturer Part Number: 7M-12.000MAAJ-T; 2nd source part number: 184-2056; Note: XTAL SMD 12.000MHz; Artikkelnr Noca: 22019166; Artikkelnr Simpro: N.A.

## Sheet sheet5_buttons_and_leds.SchDoc: Buttons and LEDs
size A4; Organization: Nordic Semiconductor; DocumentNumber: 5; Revision: 2.0.0; SheetNumber: 5; SheetTotal: 7; CompanyName: Nordic Semiconductor; DrawnBy: KJP/RUBR/GETR; ProjectNumber: 4397; PCBRevision: 0111GETR; DocumentSize: A4; PCAName: PCA10040; PCBNumber: 400150
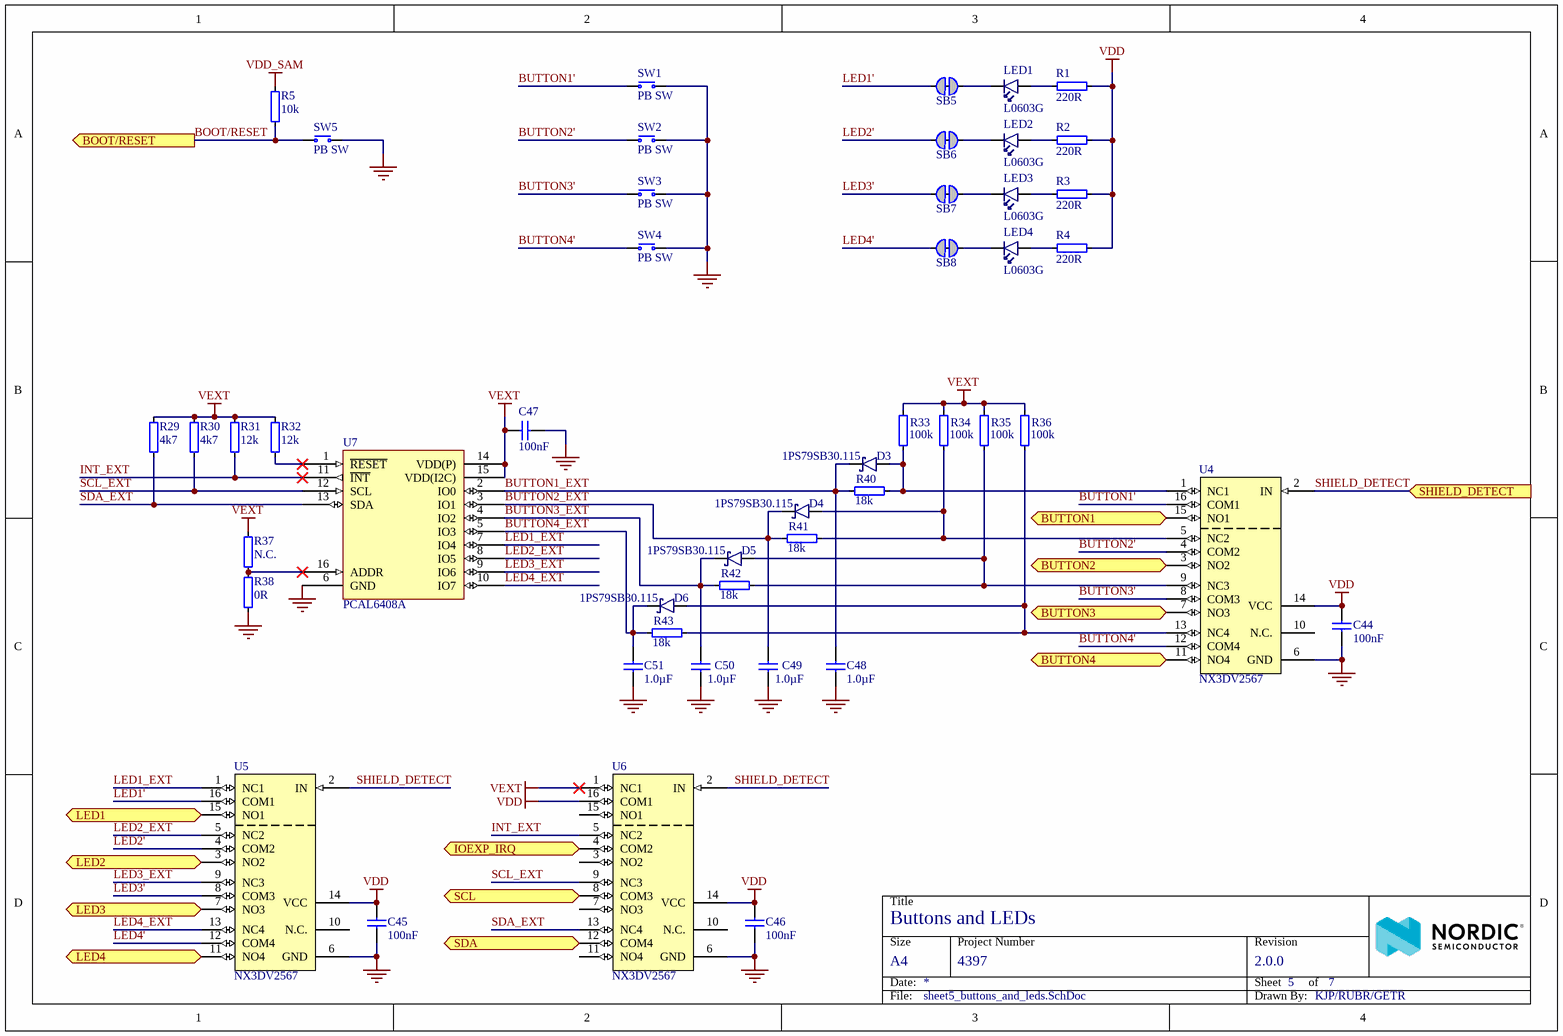
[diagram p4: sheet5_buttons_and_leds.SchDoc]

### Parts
C44  100nF  [CAPC1005X04L]
C45  100nF  [CAPC1005X04L]
C46  100nF  [CAPC1005X04L]
C47  100nF  [CAPC1005X04L]
C48  1.0µF  [CAPC1005X04L]
C49  1.0µF  [CAPC1005X04L]
C50  1.0µF  [CAPC1005X04L]
C51  1.0µF  [CAPC1005X04L]
D3  1PS79SB30.115  [SOD-523]
D4  1PS79SB30.115  [SOD-523]
D5  1PS79SB30.115  [SOD-523]
D6  1PS79SB30.115  [SOD-523]
LED1  L0603G  [LED_0603_G]
LED2  L0603G  [LED_0603_G]
LED3  L0603G  [LED_0603_G]
LED4  L0603G  [LED_0603_G]
R1  220R  [RESC1005X04L]
R2  220R  [RESC1005X04L]
R3  220R  [RESC1005X04L]
R4  220R  [RESC1005X04L]
R5  10k  [RESC1005X04L]
R29  4k7  [RESC1005X04L]
R30  4k7  [RESC1005X04L]
R31  12k  [RESC1005X04L]
R32  12k  [RESC1005X04L]
R33  100k  [RESC1005X04L]
R34  100k  [RESC1005X04L]
R35  100k  [RESC1005X04L]
R36  100k  [RESC1005X04L]
R37  N.C.  [RESC1005X04L]
R38  0R  [RESC1005X04L]
R40  18k  [RESC1005X04L]
R41  18k  [RESC1005X04L]
R42  18k  [RESC1005X04L]
R43  18k  [RESC1005X04L]
SB5  Solderbridge  [Solderbridge_Shorted]  (value not drawn)  (net tie, no BOM)
SB6  Solderbridge  [Solderbridge_Shorted]  (value not drawn)  (net tie, no BOM)
SB7  Solderbridge  [Solderbridge_Shorted]  (value not drawn)  (net tie, no BOM)
SB8  Solderbridge  [Solderbridge_Shorted]  (value not drawn)  (net tie, no BOM)
SW1  PB SW  [Switch-PB-6.2x6.3mm-SMD]
SW2  PB SW  [Switch-PB-6.2x6.3mm-SMD]
SW3  PB SW  [Switch-PB-6.2x6.3mm-SMD]
SW4  PB SW  [Switch-PB-6.2x6.3mm-SMD]
SW5  PB SW  [Switch-PB-6.2x6.3mm-SMD]
U4  NX3DV2567  [XQFN40P180X260X50-16N]
U5  NX3DV2567  [XQFN40P180X260X50-16N]
U6  NX3DV2567  [XQFN40P180X260X50-16N]
U7  PCAL6408A  [XQFN40P180X260X50-16N]

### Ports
BOOT/RESET (out), BUTTON1 (bidir), BUTTON2 (bidir), BUTTON3 (bidir), BUTTON4 (bidir), IOEXP_IRQ (bidir), LED1 (bidir), LED2 (bidir), LED3 (bidir), LED4 (bidir), SCL (bidir), SDA (bidir), SHIELD_DETECT (in)

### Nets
GND: C44.1 C45.1 C46.1 C47.1 C48.2 C49.1 C50.1 C51.2 R38.1 SW1.1(N.O) SW2.1(N.O) SW3.1(N.O) SW4.1(N.O) SW5.1(N.O) U4.6(GND) U5.6(GND) U6.6(GND) U7.6(GND)
VDD: C44.2 C45.2 C46.2 R1.2 R2.2 R3.2 R4.2 U4.14(VCC) U5.14(VCC) U6.14(VCC) U6.16(COM1)
VDD_SAM: R5.2
VEXT: C47.2 R29.2 R30.2 R31.2 R32.2 R33.2 R34.2 R35.2 R36.2 R37.2 U6.1(NC1) U7.14(VDD(P)) U7.15(VDD(I2C))
BOOT/RESET: R5.1 SW5.2(COM) ; port BOOT/RESET
BUTTON1': SW1.2(COM) U4.16(COM1)
BUTTON1_EXT: C48.1 D3.3(C) R40.1 U7.2(IO0)
BUTTON2': SW2.2(COM) U4.4(COM2)
BUTTON2_EXT: C49.2 D4.3(C) R41.1 U7.3(IO1)
BUTTON3': SW3.2(COM) U4.8(COM3)
BUTTON3_EXT: C50.2 D5.3(C) R42.1 U7.4(IO2)
BUTTON4': SW4.2(COM) U4.12(COM4)
BUTTON4_EXT: C51.1 D6.3(C) R43.1 U7.5(IO3)
INT_EXT: R31.1 U6.5(NC2) U7.11(~{INT})
IOEXP_IRQ: U6.4(COM2) ; port IOEXP_IRQ
LED1': SB5.1 U5.16(COM1)
LED1_EXT: U5.1(NC1) U7.7(IO4)
LED2': SB6.1 U5.4(COM2)
LED2_EXT: U5.5(NC2) U7.8(IO5)
LED3': SB7.1 U5.8(COM3)
LED3_EXT: U5.9(NC3) U7.9(IO6)
LED4': SB8.1 U5.12(COM4)
LED4_EXT: U5.13(NC4) U7.10(IO7)
P0.13: U4.15(NO1) ; port BUTTON1
P0.14: U4.3(NO2) ; port BUTTON2
P0.15: U4.7(NO3) ; port BUTTON3
P0.16: U4.11(NO4) ; port BUTTON4
P0.17: U5.15(NO1) ; port LED1
P0.18: U5.3(NO2) ; port LED2
P0.19: U5.7(NO3) ; port LED3
P0.20: U5.11(NO4) ; port LED4
P0.26: U6.12(COM4) ; port SDA
P0.27: U6.8(COM3) ; port SCL
SCL_EXT: R30.1 U6.9(NC3) U7.12(SCL)
SDA_EXT: R29.1 U6.13(NC4) U7.13(SDA)
SHIELD_DETECT: U4.2(IN) U5.2(IN) U6.2(IN) ; port SHIELD_DETECT
NetD3_1: D3.1(A) R33.1 R40.2 U4.1(NC1)
NetD4_1: D4.1(A) R34.1 R41.2 U4.5(NC2)
NetD5_1: D5.1(A) R35.1 R42.2 U4.9(NC3)
NetD6_1: D6.1(A) R36.1 R43.2 U4.13(NC4)
NetLED1_1: LED1.1(C) SB5.2
NetLED1_2: LED1.2(A) R1.1
NetLED2_1: LED2.1(C) SB6.2
NetLED2_2: LED2.2(A) R2.1
NetLED3_1: LED3.1(C) SB7.2
NetLED3_2: LED3.2(A) R3.1
NetLED4_1: LED4.1(C) SB8.2
NetLED4_2: LED4.2(A) R4.1
NetR32_1: R32.1 U7.1(~{RESET})
NetR37_1: R37.1 R38.2 U7.16(ADDR)

Not connected (* = marked no-connect by the designer): U4 10(N.C.); U5 10(N.C.); U6 3(NO2) 7(NO3) 10(N.C.) 11(NO4) 15(NO1)

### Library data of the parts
C44-C47 = C0402-100n: as C4 on sheet sheet2_radio
C48-C51 = C0402-1µ0: Capacitor, X5R, ±5%; Part number IPS: 00000007786; Note: 6.3V; Artikkelnr Noca: 20039235; Artikkelnr Simpro: N.A.
D3-D6 = 1PS79SB30.115: Diode Schottky Vf=0.38, Vr=40V, If=200mA, Ir=500nA; Manufacturer: NXP; 2nd source part number: 873-4097; Artikkelnr Noca: 10029120; Artikkelnr Simpro: N.A.
LED1-LED4 = LG L29K Smartled Green: LED SMARTLED GREEN 570NM 0603; Manufacturer: Osram; Manufacturer Part Number: LG L29K-G2J1-24-Z; 2nd source part number: 720-LGL29KG2J124Z; Note: 2,24..5.6 mcd, Vfmin=1.7V; Artikkelnr Noca: 13019147; Artikkelnr Simpro: N.A.
R1-R4 = R0402-220: Resistor, ±1%, 0.063W; Note: Chip Res 1%; Artikkelnr Noca: 27049057; Artikkelnr Simpro: N.A.; Value Ohm: 220
R5 = R0402-10k: as R8 on sheet sheet4_interface_mcu
R29 R30 = R0402-4k7: Resistor, ±1%, 0.063W; Part number IPS: 00000003433; Note: Chip Res 1%; Artikkelnr Noca: 27049089; Artikkelnr Simpro: N.A.; Value Ohm: 4700
R31 R32 = R0402-12k: Resistor, ±1%, 0.063W; Note: Chip Res 1%; Artikkelnr Noca: 27049099; Artikkelnr Simpro: N.A.; Value Ohm: 12000
R33-R36 = R0402-100k: Resistor, ±1%, 0.063W; Part number IPS: 00000003667; Note: Chip Res 1%; Artikkelnr Noca: 27049121; Artikkelnr Simpro: N.A.; Value Ohm: 100000
R37 = R0402-N.C.: Not mounted; Note: Chip Res; Artikkelnr Noca: N.A.; Assembly: Not mounted
R38 = R0402-0R: as R7 on sheet sheet4_interface_mcu
R40-R43 = R0402-18k: Resistor, ±1%, 0.063W; Part number IPS: 00000003300; Note: Chip Res 1%; Artikkelnr Noca: 27049103; Artikkelnr Simpro: N.A.; Value Ohm: 18000
SB5-SB8 = Solderbridge Shorted: as SB1 on sheet sheet2_radio
SW1-SW5 = Switch-PB-6.2x6.3mm-SMD: Tactile Switch, SPNO, SMD, 160gf, 6.2x6.3x2.5mm; Manufacturer: Dailywell; Manufacturer Part Number: TS604VM1-025BR-R; 2nd source part number: 688-SKHUALE010; Part number IPS: 00000007812; Artikkelnr Noca: 50019106; Artikkelnr Simpro: N.A.
U4-U6 = NX3DV2567GU: as U10 on sheet sheet4_interface_mcu
U7 = PCAL6408AHK: 8-bit I2C-bus I/O expander with interrupt output; Manufacturer: NXP Semiconductors; 2nd source part number: 771-PCAL6408AHKX; Artikkelnr Noca: 15079321; Artikkelnr Simpro: N.A.

## Sheet sheet6_connectors.SchDoc: Connectors
size A3; Organization: Nordic Semiconductor; DocumentNumber: 6; Revision: 2.0.0; SheetNumber: 6; SheetTotal: 7; CompanyName: Nordic Semiconductor; DrawnBy: KJP/RUBR/GETR; ProjectNumber: 4397; PCAName: PCA10040; PCBRevision: 0111GETR; DocumentSize: A3; PCBNumber: 400150
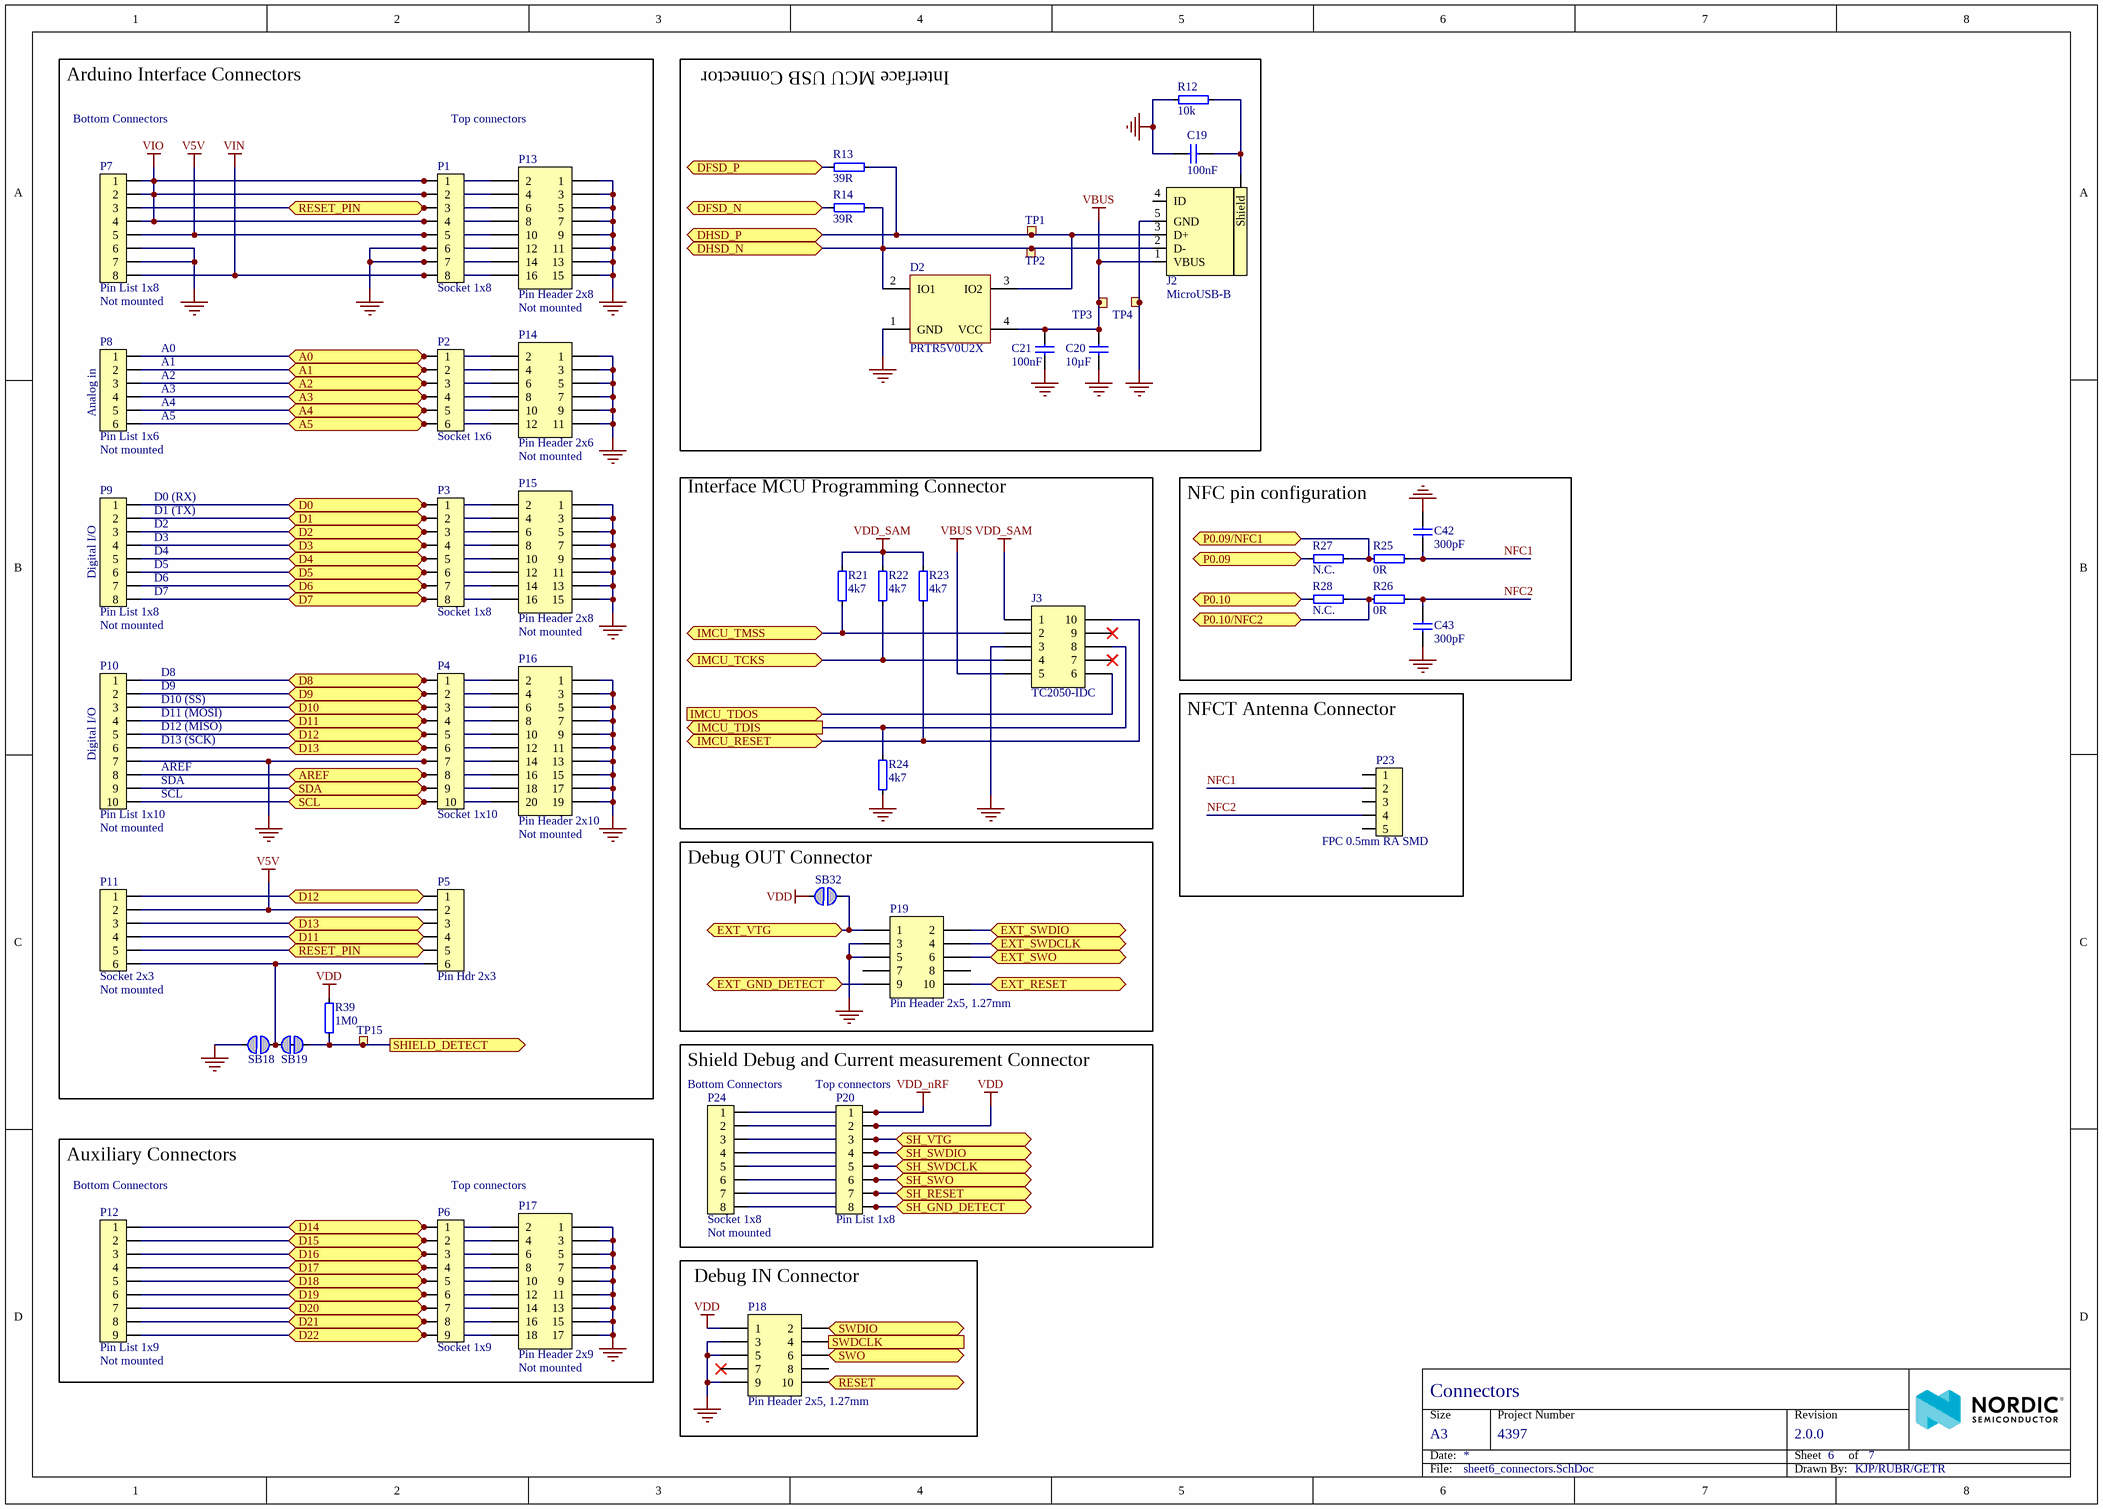
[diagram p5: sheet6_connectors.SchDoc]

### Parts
C19  100nF  [CAPC1005X04L]
C20  10µF  [CAPC1608X06L]
C21  100nF  [CAPC1005X04L]
C42  300pF  [CAPC1005X04L]
C43  300pF  [CAPC1005X04L]
D2  PRTR5V0U2X  [SOT190P230X110-4L]
J2  MicroUSB-B  [USB-Micro-B-RA-SMD-PiP]
J3  TC2050-IDC  [TC2050-IDC-NLFP]  (no BOM)
P1  Socket 1x8  [SOCKET_1x8_SMD]
P2  Socket 1x6  [SOCKET_1x6_SMD]
P3  Socket 1x8  [SOCKET_1x8_SMD]
P4  Socket 1x10  [SOCKET_1x10_SMD]
P5  Pin Hdr 2x3  [HDR_2x3-SMD]
P6  Socket 1x9  [SOCKET_1x9_SMD]
P7  Pin List 1x8  Assembly: Not mounted  [LIST_1x8_SMD-NC]
P8  Pin List 1x6  Assembly: Not mounted  [LIST_1x6_SMD-NC]
P9  Pin List 1x8  Assembly: Not mounted  [LIST_1x8_SMD-NC]
P10  Pin List 1x10  Assembly: Not mounted  [LIST_1x10_SMD-NC]
P11  Socket 2x3  Assembly: Not mounted  [SOCKET_2x3_SMD-2.54mm-bottom-NC]
P12  Pin List 1x9  Assembly: Not mounted  [LIST_1x9_SMD-NC]
P13  Pin Header 2x8  Assembly: Not mounted  [HDR_2x8-NC]
P14  Pin Header 2x6  Assembly: Not mounted  [HDR_2x6-NC]
P15  Pin Header 2x8  Assembly: Not mounted  [HDR_2x8-NC]
P16  Pin Header 2x10  Assembly: Not mounted  [HDR_2x10-NC]
P17  Pin Header 2x9  Assembly: Not mounted  [HDR_2x9-NC]
P18  Pin Header 2x5, 1.27mm  [HDR_2x5-SMD-1.27mm-K]
P19  Pin Header 2x5, 1.27mm  [HDR_2x5-SMD-1.27mm-K]
P20  Pin List 1x8  [LIST_1x8_SMD]
P23  FPC 0.5mm RA SMD  [FPC_05P-0.5mm-RA-SMD]
P24  Socket 1x8  Assembly: Not mounted  [LIST_1x8_SMD-NC]
R12  10k  [RESC1005X04L]
R13  39R  [RESC1005X04L]
R14  39R  [RESC1005X04L]
R21  4k7  [RESC1005X04L]
R22  4k7  [RESC1005X04L]
R23  4k7  [RESC1005X04L]
R24  4k7  [RESC1005X04L]
R25  0R  [RESC1005X04L]
R26  0R  [RESC1005X04L]
R27  N.C.  [RESC1005X04L]
R28  N.C.  [RESC1005X04L]
R39  1M0  [RESC1005X04L]
SB18  Solderbridge  [Solderbridge]  (value not drawn)  (no BOM)
SB19  Solderbridge  [Solderbridge_Shorted]  (value not drawn)  (net tie, no BOM)
SB32  Solderbridge  [Solderbridge]  (value not drawn)  (no BOM)
TP1  Ø1.0mm,SMD  [TP_SMD_Ø1.0mm]  (value not drawn)  (no BOM)
TP2  Ø1.0mm,SMD  [TP_SMD_Ø1.0mm]  (value not drawn)  (no BOM)
TP3  Ø1.0mm,SMD  [TP_SMD_Ø1.0mm]  (value not drawn)  (no BOM)
TP4  Ø1.0mm,SMD  [TP_SMD_Ø1.0mm]  (value not drawn)  (no BOM)
TP15  Ø1.0mm,SMD  [TP_SMD_Ø1.0mm]  (value not drawn)  (no BOM)

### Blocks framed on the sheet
Arduino Interface Connectors: P1-P5 P7-P11 P13-P16 R39 SB18 SB19 TP15
Interface MCU USB Connector: C19-C21 D2 J2 R12-R14 TP1-TP4
Interface MCU Programming Connector: J3 R21-R24
NFC pin configuration: C42 C43 R25-R28
NFCT Antenna Connector: P23
Debug OUT Connector: P19 SB32
Shield Debug and Current measurement Connector: P20 P24
Auxiliary Connectors: P6 P12 P17
Debug IN Connector: P18

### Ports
A0 (bidir), A1 (bidir), A2 (bidir), A3 (bidir), A4 (bidir), A5 (bidir), AREF (bidir), D0 (bidir), D1 (bidir), D2 (bidir), D3 (bidir), D4 (bidir), D5 (bidir), D6 (bidir), D7 (bidir), D8 (bidir), D9 (bidir), D10 (bidir), D11 (bidir), D12 (bidir), D13 (bidir), D14 (bidir), D15 (bidir), D16 (bidir), D17 (bidir), D18 (bidir), D19 (bidir), D20 (bidir), D21 (bidir), D22 (bidir), DFSD_N (bidir), DFSD_P (bidir), DHSD_N (bidir), DHSD_P (bidir), EXT_GND_DETECT (bidir), EXT_RESET (bidir), EXT_SWDCLK (bidir), EXT_SWDIO (bidir), EXT_SWO (bidir), EXT_VTG (bidir), IMCU_RESET (bidir), IMCU_TCKS (bidir), IMCU_TDIS (out), IMCU_TDOS (in), IMCU_TMSS (bidir), P0.09 (bidir), P0.09/NFC1 (bidir), P0.10 (bidir), P0.10/NFC2 (bidir), RESET (bidir), RESET_PIN (bidir), SCL (bidir), SDA (bidir), SH_GND_DETECT (bidir), SH_RESET (bidir), SH_SWDCLK (bidir), SH_SWDIO (bidir), SH_SWO (bidir), SH_VTG (bidir), SHIELD_DETECT (out), SWDCLK (out), SWDIO (bidir), SWO (bidir)

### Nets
GND: C19.1 C20.1 C21.1 C42.2 C43.1 D2.1(GND) J2.5(GND) J3.3 P1.6 P1.7 P4.7 P7.6 P7.7 P10.7 P13.1 P13.3 P13.5 P13.7 P13.9 P13.11 P13.12 P13.13 P13.14 P13.15 P14.1 P14.3 P14.5 P14.7 P14.9 P14.11 P15.1 P15.3 P15.5 P15.7 P15.9 P15.11 P15.13 P15.15 P16.1 P16.3 P16.5 P16.7 P16.9 P16.11 P16.13 P16.14 P16.15 P16.17 P16.19 P17.1 P17.3 P17.5 P17.7 P17.9 P17.11 P17.13 P17.15 P17.17 P18.3 P18.5 P18.9 P19.3 P19.5 R12.1 R24.2 SB18.1 TP4.1
V5V: P1.5 P5.2 P7.5 P11.2 P13.10
VBUS: C20.2 C21.2 D2.4(VCC) J2.1(VBUS) J3.5 TP3.1
VDD: P18.1 P20.2 P24.2 R39.2 SB32.1
VDD_nRF: P20.1 P24.1
VDD_SAM: J3.1 R21.2 R22.2 R23.2
VIN: P1.8 P7.8 P13.16
VIO: P1.1 P1.2 P1.4 P7.1 P7.2 P7.4 P13.2 P13.4 P13.8
D17: P6.4 P12.4 P17.8 ; port D17
D18: P6.5 P12.5 P17.10 ; port D18
D19: P6.6 P12.6 P17.12 ; port D19
D20: P6.7 P12.7 P17.14 ; port D20
D21: P6.8 P12.8 P17.16 R27.1 ; port D21, port P0.09
D22: P6.9 P12.9 P17.18 R28.1 ; port D22, port P0.10
DFSD_N: R14.1 ; port DFSD_N
DFSD_P: R13.1 ; port DFSD_P
DHSD_N: D2.2(IO1) J2.2(D-) R14.2 TP2.1 ; port DHSD_N
DHSD_P: D2.3(IO2) J2.3(D+) R13.2 TP1.1 ; port DHSD_P
EXT_GND_DETECT: P19.9 ; port EXT_GND_DETECT
EXT_RESET: P19.10 ; port EXT_RESET
EXT_SWDCLK: P19.4 ; port EXT_SWDCLK
EXT_SWDIO: P19.2 ; port EXT_SWDIO
EXT_SWO: P19.6 ; port EXT_SWO
EXT_VTG: P19.1 SB32.2 ; port EXT_VTG
IMCU_RESET: J3.10 R23.1 ; port IMCU_RESET
IMCU_TCKS: J3.4 R22.1 ; port IMCU_TCKS
IMCU_TDIS: J3.8 R24.1 ; port IMCU_TDIS
IMCU_TDOS: J3.6 ; port IMCU_TDOS
IMCU_TMSS: J3.2 R21.1 ; port IMCU_TMSS
NFC1: C42.1 P23.2 R25.1
NFC2: C43.2 P23.4 R26.1
P0.00: P6.1 P12.1 P17.2 ; port D14
P0.01: P6.2 P12.2 P17.4 ; port D15
P0.02: P4.8 P10.8 P16.16 ; port AREF
P0.03: P2.1 P8.1 P14.2 ; port A0
P0.04: P2.2 P8.2 P14.4 ; port A1
P0.09/NFC1: R25.2 R27.2 ; port P0.09/NFC1
P0.10/NFC2: R26.2 R28.2 ; port P0.10/NFC2
P0.11: P3.1 P9.1 P15.2 ; port D0
P0.12: P3.2 P9.2 P15.4 ; port D1
P0.13: P3.3 P9.3 P15.6 ; port D2
P0.14: P3.4 P9.4 P15.8 ; port D3
P0.15: P3.5 P9.5 P15.10 ; port D4
P0.16: P3.6 P9.6 P15.12 ; port D5
P0.17: P3.7 P9.7 P15.14 ; port D6
P0.18: P3.8 P9.8 P15.16 P18.6 ; port SWO, port D7
P0.19: P4.1 P10.1 P16.2 ; port D8
P0.20: P4.2 P10.2 P16.4 ; port D9
P0.21: P6.3 P12.3 P17.6 P18.10 ; port RESET, port D16
P0.22: P4.3 P10.3 P16.6 ; port D10
P0.23: P4.4 P5.4 P10.4 P11.4 P16.8 ; port D11
P0.24: P4.5 P5.1 P10.5 P11.1 P16.10 ; port D12
P0.25: P4.6 P5.3 P10.6 P11.3 P16.12 ; port D13
P0.26: P4.9 P10.9 P16.18 ; port SDA
P0.27: P4.10 P10.10 P16.20 ; port SCL
P0.28: P2.3 P8.3 P14.6 ; port A2
P0.29: P2.4 P8.4 P14.8 ; port A3
P0.30: P2.5 P8.5 P14.10 ; port A4
P0.31: P2.6 P8.6 P14.12 ; port A5
RESET_PIN: P1.3 P5.5 P7.3 P11.5 P13.6 ; port RESET_PIN
SH_GND_DETECT: P20.8 P24.8 ; port SH_GND_DETECT
SH_RESET: P20.7 P24.7 ; port SH_RESET
SH_SWDCLK: P20.5 P24.5 ; port SH_SWDCLK
SH_SWDIO: P20.4 P24.4 ; port SH_SWDIO
SH_SWO: P20.6 P24.6 ; port SH_SWO
SH_VTG: P20.3 P24.3 ; port SH_VTG
SHIELD_DETECT: R39.1 SB19.2 TP15.1 ; port SHIELD_DETECT
SWDCLK: P18.4 ; port SWDCLK
SWDIO: P18.2 ; port SWDIO
NetC19_2: C19.2 J2.6(Shield) R12.2
NetP5_6: P5.6 P11.6 SB18.2 SB19.1

Not connected (* = marked no-connect by the designer): J2 4(ID); J3 7* 9*; P18 7* 8; P19 7 8; P23 1 3 5

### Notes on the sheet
- Bottom Connectors
- Top connectors
- (near P8) A0
- (near P8) A1
- (near P8) A2
- (near P8) Analog in
- (near P8) A3
- (near P8) A4
- (near P8) A5
- (near P9) D0 (RX)
- (near P9) D1 (TX)
- (near P9) Digital I/O
- (near P9) D2
- (near P9) D3
- (near P9) D4
- (near P9) D5
- (near P9) D6
- (near P9) D7
- (near P10) D8
- (near P10) D9
- (near P10) D10 (SS)
- (near P10) D11 (MOSI)
- (near P10) Digital I/O
- (near P10) AREF
- (near P10) D12 (MISO)
- (near P10) D13 (SCK)
- (near P10) SDA
- (near P10) SCL
- (near P24) Bottom Connectors
- (near P20) Top connectors
- (near P12) Bottom Connectors

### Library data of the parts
C19 C21 = C0402-100n: as C4 on sheet sheet2_radio
C20 = C0603-10µ: as C31 on sheet sheet4_interface_mcu
C42 C43 = C0402-300p: Capacitor, NP0, ±5%; Note: 50V; Artikkelnr Noca: 20020004; Artikkelnr Simpro: N.A.
D2 = PRTR5V0U2X: Ultra low capacitance double rail-to-rail ESD protection diode; Manufacturer: NXP; 2nd source part number: 152-4157; Artikkelnr Noca: 10069015; Artikkelnr Simpro: N.A.
J2 = USB-Micro-B-RA-SMD-PiP: MicroUSB-B-SMT; Manufacturer: Allen Creations Corp.; Manufacturer Part Number: AJU55-BS2111-L; 2nd source part number: 609-4616-1-ND; Part number IPS: 00000007790; Artikkelnr Noca: 55029020; Artikkelnr Simpro: N.A.
J3 = TC2050-IDC-NLFP: CBL PLUG-OF-NAILS 10-PIN; Manufacturer: Tag-Connect LLC; Artikkelnr Noca: N.A.
P1 P3 = Socket 1x8 SMD: Socket 1x8, 2.54mm (100mil), SMD; Manufacturer: W-CON; Manufacturer Part Number: 2171-108MS0CUNR1; 2nd source part number: SSM-108-F-SV-P-TR; Artikkelnr Noca: 55030002; Artikkelnr Simpro: N.A.
P2 = Socket 1x6 SMD: Socket 1x6, 2.54mm (100mil), SMD; Manufacturer: W-CON; Manufacturer Part Number: 2171-106MS0CUNR1; 2nd source part number: SSM-106-F-SV-P-TR; Artikkelnr Noca: 55030001; Artikkelnr Simpro: N.A.
P4 = Socket 1x10 SMD: Socket 1x10, 2.54mm (100mil), SMD; Manufacturer: W-CON; Manufacturer Part Number: 2171-110MS0CUNR1; 2nd source part number: SSM-110-F-SV-P-TR; Artikkelnr Noca: 55030004; Artikkelnr Simpro: N.A.
P5 = Pin Header 2x3 SMD: Pin Header 2x3, 2.54mm (100mil) SMD; Manufacturer: W-CON; Manufacturer Part Number: 1125-1203S0M116R1; 2nd source part number: TSM-103-01-L-DV; Artikkelnr Noca: 55010007; Artikkelnr Simpro: N.A.
P6 = Socket 1x9 SMD: Socket 1x9, 2.54mm (100mil), SMD; Manufacturer: W-CON; Manufacturer Part Number: 2171-109MS0CUNR1; 2nd source part number: SSM-109-L-SV; Artikkelnr Noca: 55030003; Artikkelnr Simpro: N.A.
P7 P9 = Pin List 1x8 SMD, N.C.: Pin List 1x8, 2.54mm (100mil), SMD; Manufacturer: W-CON; Manufacturer Part Number: 1125-1108S0M116R2; Part number IPS: N.A.; Artikkelnr Noca: 55010006
P8 = Pin List 1x6 SMD, N.C.: Pin List 1x6, 2.54mm (100mil), SMD; Manufacturer: W-CON; Manufacturer Part Number: 1125-1106S0M116R2; Part number IPS: N.A.; Artikkelnr Noca: 55010026
P10 = Pin List 1x10 SMD, N.C.: Pin List 1x10, 2.54mm (100mil), SMD; Manufacturer: W-CON; Manufacturer Part Number: 1125-1110S0M116R2; Part number IPS: N.A.; Artikkelnr Noca: 55010028
P11 = Socket 2x3 SMD Bottom, N.C.: Socket 2x3, 2.54mm (100mil), SMD; Manufacturer: W-CON; Manufacturer Part Number: 2171-203MS0CUNR1; Part number IPS: N.A.; Artikkelnr Noca: 55030010
P12 = Pin List 1x9 SMD, N.C.: Pin List 1x9, 2.54mm (100mil), SMD; Manufacturer: W-CON; Manufacturer Part Number: 1125-1109S0M116R2; Part number IPS: N.A.; Artikkelnr Noca: 55010024
P13 P15 = Pin Header 2x8, N.C.: Pin Header 2x8, 2.54mm (100mil); Artikkelnr Noca: N.A.
P14 = Pin Header 2x6, N.C.: Pin Header 2x6, 2.54mm (100mil); Artikkelnr Noca: N.A.
P16 = Pin Header 2x10, N.C.: Pin Header 2x10, 2.54mm (100mil); Artikkelnr Noca: N.A.
P17 = Pin Header 2x9, N.C.: Pin Header 2x9, 2.54mm (100mil); Artikkelnr Noca: N.A.
P18 P19 = Pin Header 2x5 SMD, 1.27mm, KS: Pin Header 2x5, 1.27mm (50mil), SMD, Keying Shroud; Manufacturer: W-CON; Manufacturer Part Number: 3132-10MS0BK00R1; 2nd source part number: FTSH-105-01-F-DV-K; Artikkelnr Noca: 55010009; Artikkelnr Simpro: N.A.
P20 = Pin List 1x8 SMD: Pin List 1x8, 2.54mm (100mil), SMD; Manufacturer: W-CON; Manufacturer Part Number: 1125-1108S0M116R2; Part number IPS: N.A.; Artikkelnr Noca: 55010006
P23 = FPC_05P-0.5mm-RA-SMD: 0.5mm FPC, 5P,Right Angle SMT,Double Contact,H=1.2mm,White, Tin plated; Manufacturer: W-CON; Manufacturer Part Number: 5141-05RZDNWR01; 2nd source part number: WM9836CT-ND; Part number IPS: 00000007792; Artikkelnr Noca: 55010020; Artikkelnr Simpro: N.A.
P24 = Socket 1x8 SMD, N.C.: Socket 1x8, 2.54mm (100mil), SMD; Manufacturer: W-CON; Manufacturer Part Number: 2171-108MS0CUNR1; Artikkelnr Noca: N.A.
R12 = R0402-10k: as R8 on sheet sheet4_interface_mcu
R13 R14 = R0402-39R: Resistor, ±1%, 0.063W; Part number IPS: 00000000821; Note: Chip Res 1%; Artikkelnr Noca: 27049039; Artikkelnr Simpro: N.A.; Value Ohm: 39
R21-R24 = R0402-4k7: as R29 on sheet sheet5_buttons_and_leds
R25 R26 = R0402-0R: as R7 on sheet sheet4_interface_mcu
R27 R28 = R0402-N.C.: as R37 on sheet sheet5_buttons_and_leds
R39 = R0402-1M0: Resistor, ±1%, 0.063W; Part number IPS: 00000006807; Note: Chip Res 1%; Artikkelnr Noca: 27049145; Artikkelnr Simpro: N.A.; Value Ohm: 1000000
SB18 SB32 = Solderbridge: Artikkelnr Noca: N.A.
SB19 = Solderbridge Shorted: as SB1 on sheet sheet2_radio
TP1-TP4 TP15 = TP_SMD_Ø1.0MM: as TP11 on sheet sheet3_pin_map

## Sheet sheet7_power_supply.SchDoc: Power Supply
size A4; Organization: Nordic Semiconductor; DocumentNumber: 7; Revision: 2.0.0; SheetNumber: 7; SheetTotal: 7; CompanyName: Nordic Semiconductor; DrawnBy: KJP/RUBR/GETR; ProjectNumber: 4397; PCBRevision: 0111GETR; DocumentSize: A4; PCAName: PCA10040; PCBNumber: 400150
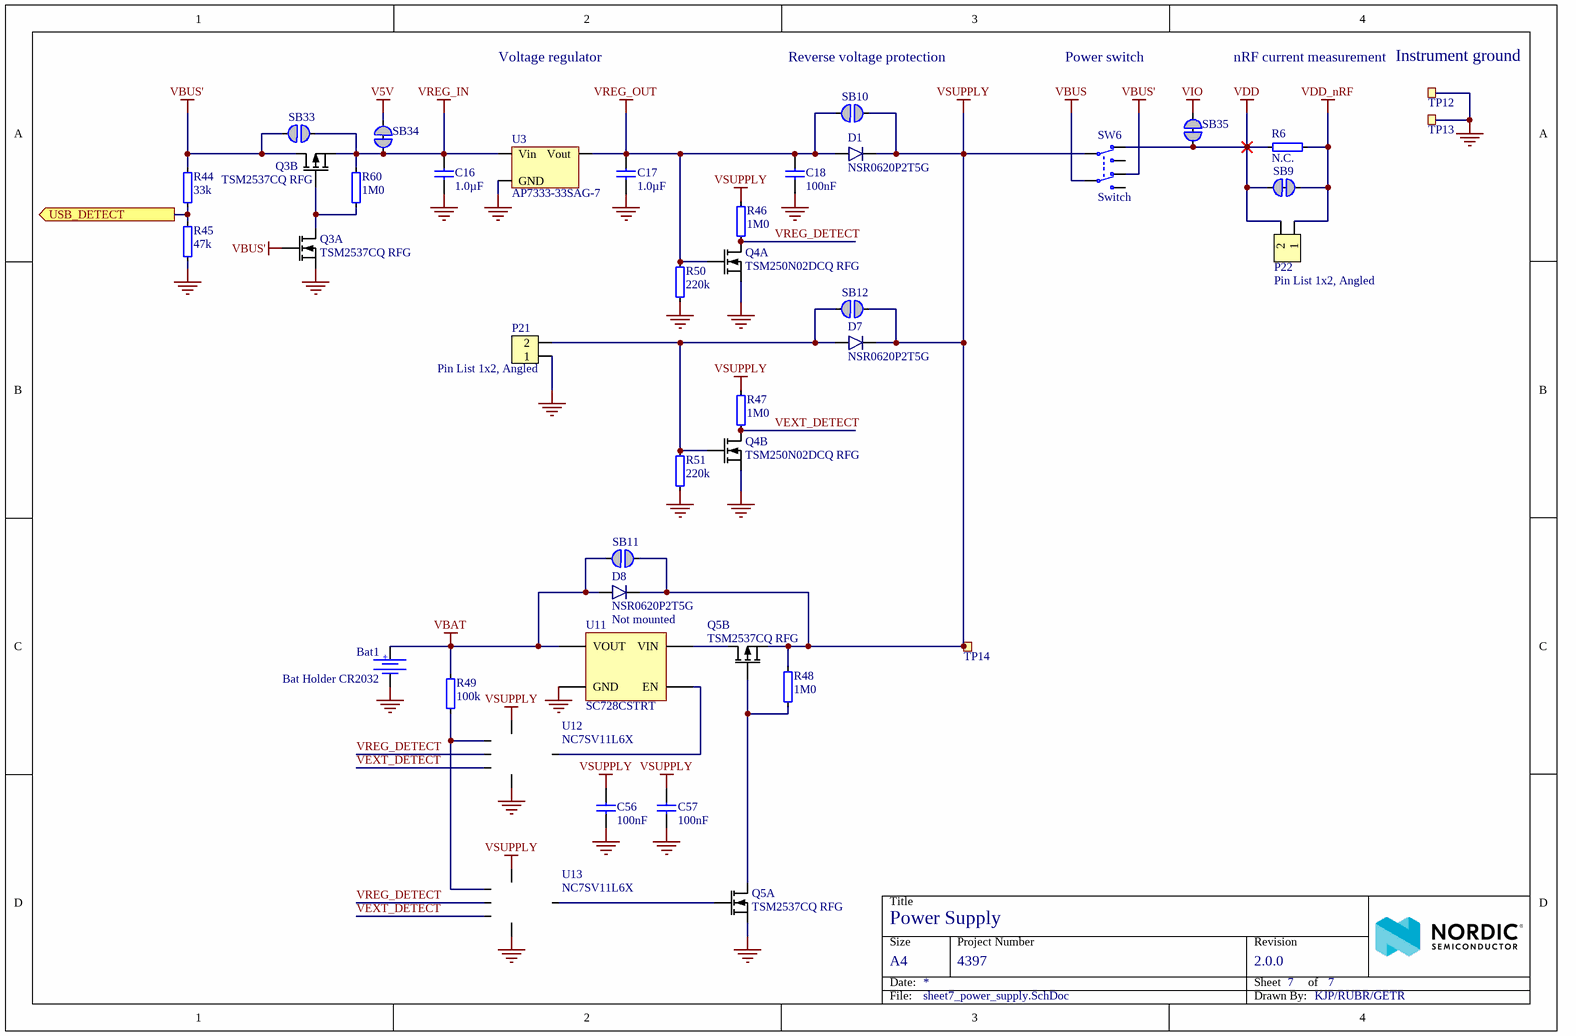
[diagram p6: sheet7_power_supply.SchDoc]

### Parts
Bat1  Bat Holder CR2032  [CR2032_HOLDER_SMD]
C16  1.0µF  [CAPC1608X06L]
C17  1.0µF  [CAPC1608X06L]
C18  100nF  [CAPC1005X04L]
C56  100nF  [CAPC0603X03L_C]
C57  100nF  [CAPC0603X03L_C]
D1  NSR0620P2T5G  [SODFL100X40-2N]
D7  NSR0620P2T5G  [SODFL100X40-2N]
D8  NSR0620P2T5G  Assembly: Not mounted  [SODFL100X40-2N]
P21  Pin List 1x2, Angled  [LIST_ANG_1x2-SMD-2.54MM]
P22  Pin List 1x2, Angled  [LIST_ANG_1x2-SMD-2.54MM]
Q3  TSM2537CQ RFG  [DFN65P200X200X80_HS-6N]  (parts A,B of 2)
Q4  TSM250N02DCQ RFG  [DFN65P200X200X80_HS-6N]  (parts A,B of 2)
Q5  TSM2537CQ RFG  [DFN65P200X200X80_HS-6N]  (parts A,B of 2)
R6  N.C.  [RESC1005X04L]
R44  33k  [RESC0603X03L_C]
R45  47k  [RESC0603X03L_C]
R46  1M0  [RESC0603X03L_C]
R47  1M0  [RESC0603X03L_C]
R48  1M0  [RESC0603X03L_C]
R49  100k  [RESC0603X03L_C]
R50  220k  [RESC0603X03L_C]
R51  220k  [RESC0603X03L_C]
R60  1M0  [RESC0603X03L_C]
SB9  Solderbridge  [Solderbridge_Shorted]  (value not drawn)  (net tie, no BOM)
SB10  Solderbridge  [Solderbridge]  (value not drawn)  (no BOM)
SB11  Solderbridge  [Solderbridge]  (value not drawn)  (no BOM)
SB12  Solderbridge  [Solderbridge]  (value not drawn)  (no BOM)
SB33  Solderbridge  [Solderbridge]  (value not drawn)  (no BOM)
SB34  Solderbridge  [Solderbridge_Shorted]  (value not drawn)  (net tie, no BOM)
SB35  Solderbridge  [Solderbridge_Shorted_Power]  (value not drawn)  (net tie, no BOM)
SW6  Switch  [Switch-Slide-DPDT-8.5x3.6mm]
TP12  TP  [TESTPAD-TH]  (value not drawn)  (no BOM)
TP13  TP  [TESTPAD-TH]  (value not drawn)  (no BOM)
TP14  Ø1.0mm,SMD  [TP_SMD_Ø1.0mm]  (value not drawn)  (no BOM)
U3  AP7333-33SAG-7  [SOT-23A]
U11  SC728CSTRT  [BGA4C40P2X2_76X76X62]
U12  NC7SV11L6X  [DFN1410-6N]
U13  NC7SV11L6X  [DFN1410-6N]

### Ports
USB_DETECT (out)

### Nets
GND: Bat1.2 C16.1 C17.1 C18.1 C56.1 C57.1 P21.1 Q3.1(S1) Q4.1(S1) Q4.4(S2) Q5.1(S1) R45.2 R50.2 R51.2 TP12.1 TP13.1 U3.3(GND) U11.B1(GND) U12.2(GND) U13.2(GND)
V5V: SB34.1
VBAT: Bat1.1 D8.2(A) R49.1 SB11.2 U11.A1(VOUT)
VBUS: SW6.5(COM-2)
VBUS': Q3.2(G1) Q3.3(D2) R44.1 SB33.2 SW6.6(N.C-2)
VDD: P22.2 R6.1 SB9.2 SB35.2 SW6.3(N.C-1)
VDD_nRF: P22.1 R6.2 SB9.1
VIO: SB35.1
VREG_IN: C16.2 Q3.4(S2) R60.1 SB33.1 SB34.2 U3.1(Vin)
VREG_OUT: C17.2 C18.2 D1.2(A) Q4.2(G1) R50.1 SB10.2 U3.2(Vout)
VSUPPLY: C56.2 C57.2 D1.1(C) D7.1(C) D8.1(C) Q5.4(S2) R46.1 R47.1 R48.1 SB10.1 SB11.1 SB12.1 SW6.2(COM-1) TP14.1 U12.5(VCC) U13.5(VCC)
USB_DETECT: R44.2 R45.1 ; port USB_DETECT
VEXT_DETECT: Q4.3(D2) R47.2 U12.6(C) U13.6(C)
VREG_DETECT: Q4.6(D1) R46.2 U12.3(B) U13.3(B)
NetD7_2: D7.2(A) P21.2 Q4.5(G2) R51.1 SB12.2
NetQ3_5: Q3.5(G2) Q3.6(D1) R60.2
NetQ5_2: Q5.2(G1) U13.4(Y)
NetQ5_3: Q5.3(D2) U11.A2(VIN)
NetQ5_5: Q5.5(G2) Q5.6(D1) R48.2
NetR49_2: R49.2 U12.1(A) U13.1(A)
NetU11_B2: U11.B2(EN) U12.4(Y)

Not connected (* = marked no-connect by the designer): SW6 1(N.O-1) 4(N.O-2)

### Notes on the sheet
- Voltage regulator
- (near SB10) Reverse voltage protection
- Power switch
- nRF current measurement
- (near TP12) Instrument ground

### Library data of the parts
Bat1 = Bat Holder CR2032 SMD: Manufacturer: Comfortable; Manufacturer Part Number: BC-2001; 2nd source part number: 165-0693; Artikkelnr Noca: 55089011; Artikkelnr Simpro: N.A.
C16 C17 = C0603-1µ0: as C10 on sheet sheet2_radio
C18 = C0402-100n: as C4 on sheet sheet2_radio
C56 C57 = C0201-100n: Capacitor, X5R, ±10%; Part number IPS: 00000001248; Note: 16V; Artikkelnr Noca: N.A.
D1 D7 D8 = NSR0620P2T5G: 20V schottky barrier diode, Vf 350 mV @ 100 mA, Ir 2.0 µA @ 10 V, If 500 mA; Manufacturer: ON Semiconductor; Part number IPS: N.A.; Artikkelnr Noca: 10029169
P21 P22 = Pin List Ang 1x2 SMD, 2.54mm: Pin List 1x2, 2.54mm (100mil), Right Angled, SMD; Manufacturer: W-CON; Manufacturer Part Number: 1125B-1102S0Z135R2; 2nd source part number: TSM-102-01-L-SH-A; Artikkelnr Noca: 55010023; Artikkelnr Simpro: N.A.
Q3 Q5 = TSM2537CQ RFG: as Q1 on sheet sheet4_interface_mcu
Q4 = TSM250N02DCQ RFG: Dual N Ch MOFET, 5.8A, 55mOhm max, 620mW; Manufacturer: Taiwan Semiconductor; Artikkelnr Noca: N.A.
R6 = R0402-N.C.: as R37 on sheet sheet5_buttons_and_leds
R44 = R0201-33k: Resistor, ±1%, 0.05W; Note: Chip Res 1%; Artikkelnr Noca: N.A.
R45 = R0201-47k: Resistor, ±1%, 0.05W; Note: Chip Res 1%; Artikkelnr Noca: N.A.
R46-R48 R60 = R0201-1M0: Resistor, ±1%, 0.05W; Note: Chip Res 1%; Artikkelnr Noca: N.A.
R49 = R0201-100k: Resistor, ±1%, 0.05W; Note: Chip Res 1%; Artikkelnr Noca: N.A.
R50 R51 = R0201-220k: Resistor, ±1%, 0.05W; Note: Chip Res 1%; Artikkelnr Noca: N.A.
SB9 SB34 = Solderbridge Shorted: as SB1 on sheet sheet2_radio
SB10-SB12 SB33 = Solderbridge: Artikkelnr Noca: N.A.
SB35 = Solderbridge Shorted Power: Shorted Solderbridge Power; Artikkelnr Noca: N.A.
SW6 = Switch-Slide-DPDT-8.5x3.6mm: SMD slide Switch (ON-ON); Manufacturer: Dailywell; Manufacturer Part Number: SS206VM-G2-LLR-R; Part number IPS: N.A.; Artikkelnr Noca: 50019107
TP12 TP13 = Testpoint TH: Testpoint, through hole; Artikkelnr Noca: N.A.
TP14 = TP_SMD_Ø1.0MM: as TP11 on sheet sheet3_pin_map
U3 = AP7333-33SAG-7: 300mA, Low Quiescent Current, Fast Transient Low Dropout Linear Regulator; Manufacturer: Diodes Incorporated; Artikkelnr Noca: 17039216; Artikkelnr Simpro: N.A.
U11 = SC728CSTRT: Semtech, 2A Low Vin, Very Low Ron, Load Switch, 4DSBGA; Manufacturer: Semtech Corporation; 2nd source part number: 947-SC728CSTRT; Artikkelnr Noca: 15070081; Artikkelnr Simpro: N.A.
U12 U13 = NC7SV11L6X: Single 3-input AND gate; Manufacturer: ON Semiconductor; Artikkelnr Noca: N.A.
